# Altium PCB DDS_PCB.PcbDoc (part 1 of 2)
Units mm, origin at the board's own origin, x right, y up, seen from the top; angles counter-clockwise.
Board outline 101.55 x 88.3 mm, 8 copper layers (TOP_L1, Plane_L2, Inner_L3, Plane_L4, Plane_L5, Inner_L6, Plane_L7, Bottom Layer_L8), stack 0.681 mm thick; 432 components, 249 nets, 1457 pads, 24 vias.
Unrouted connection lines stored in the file: 980.
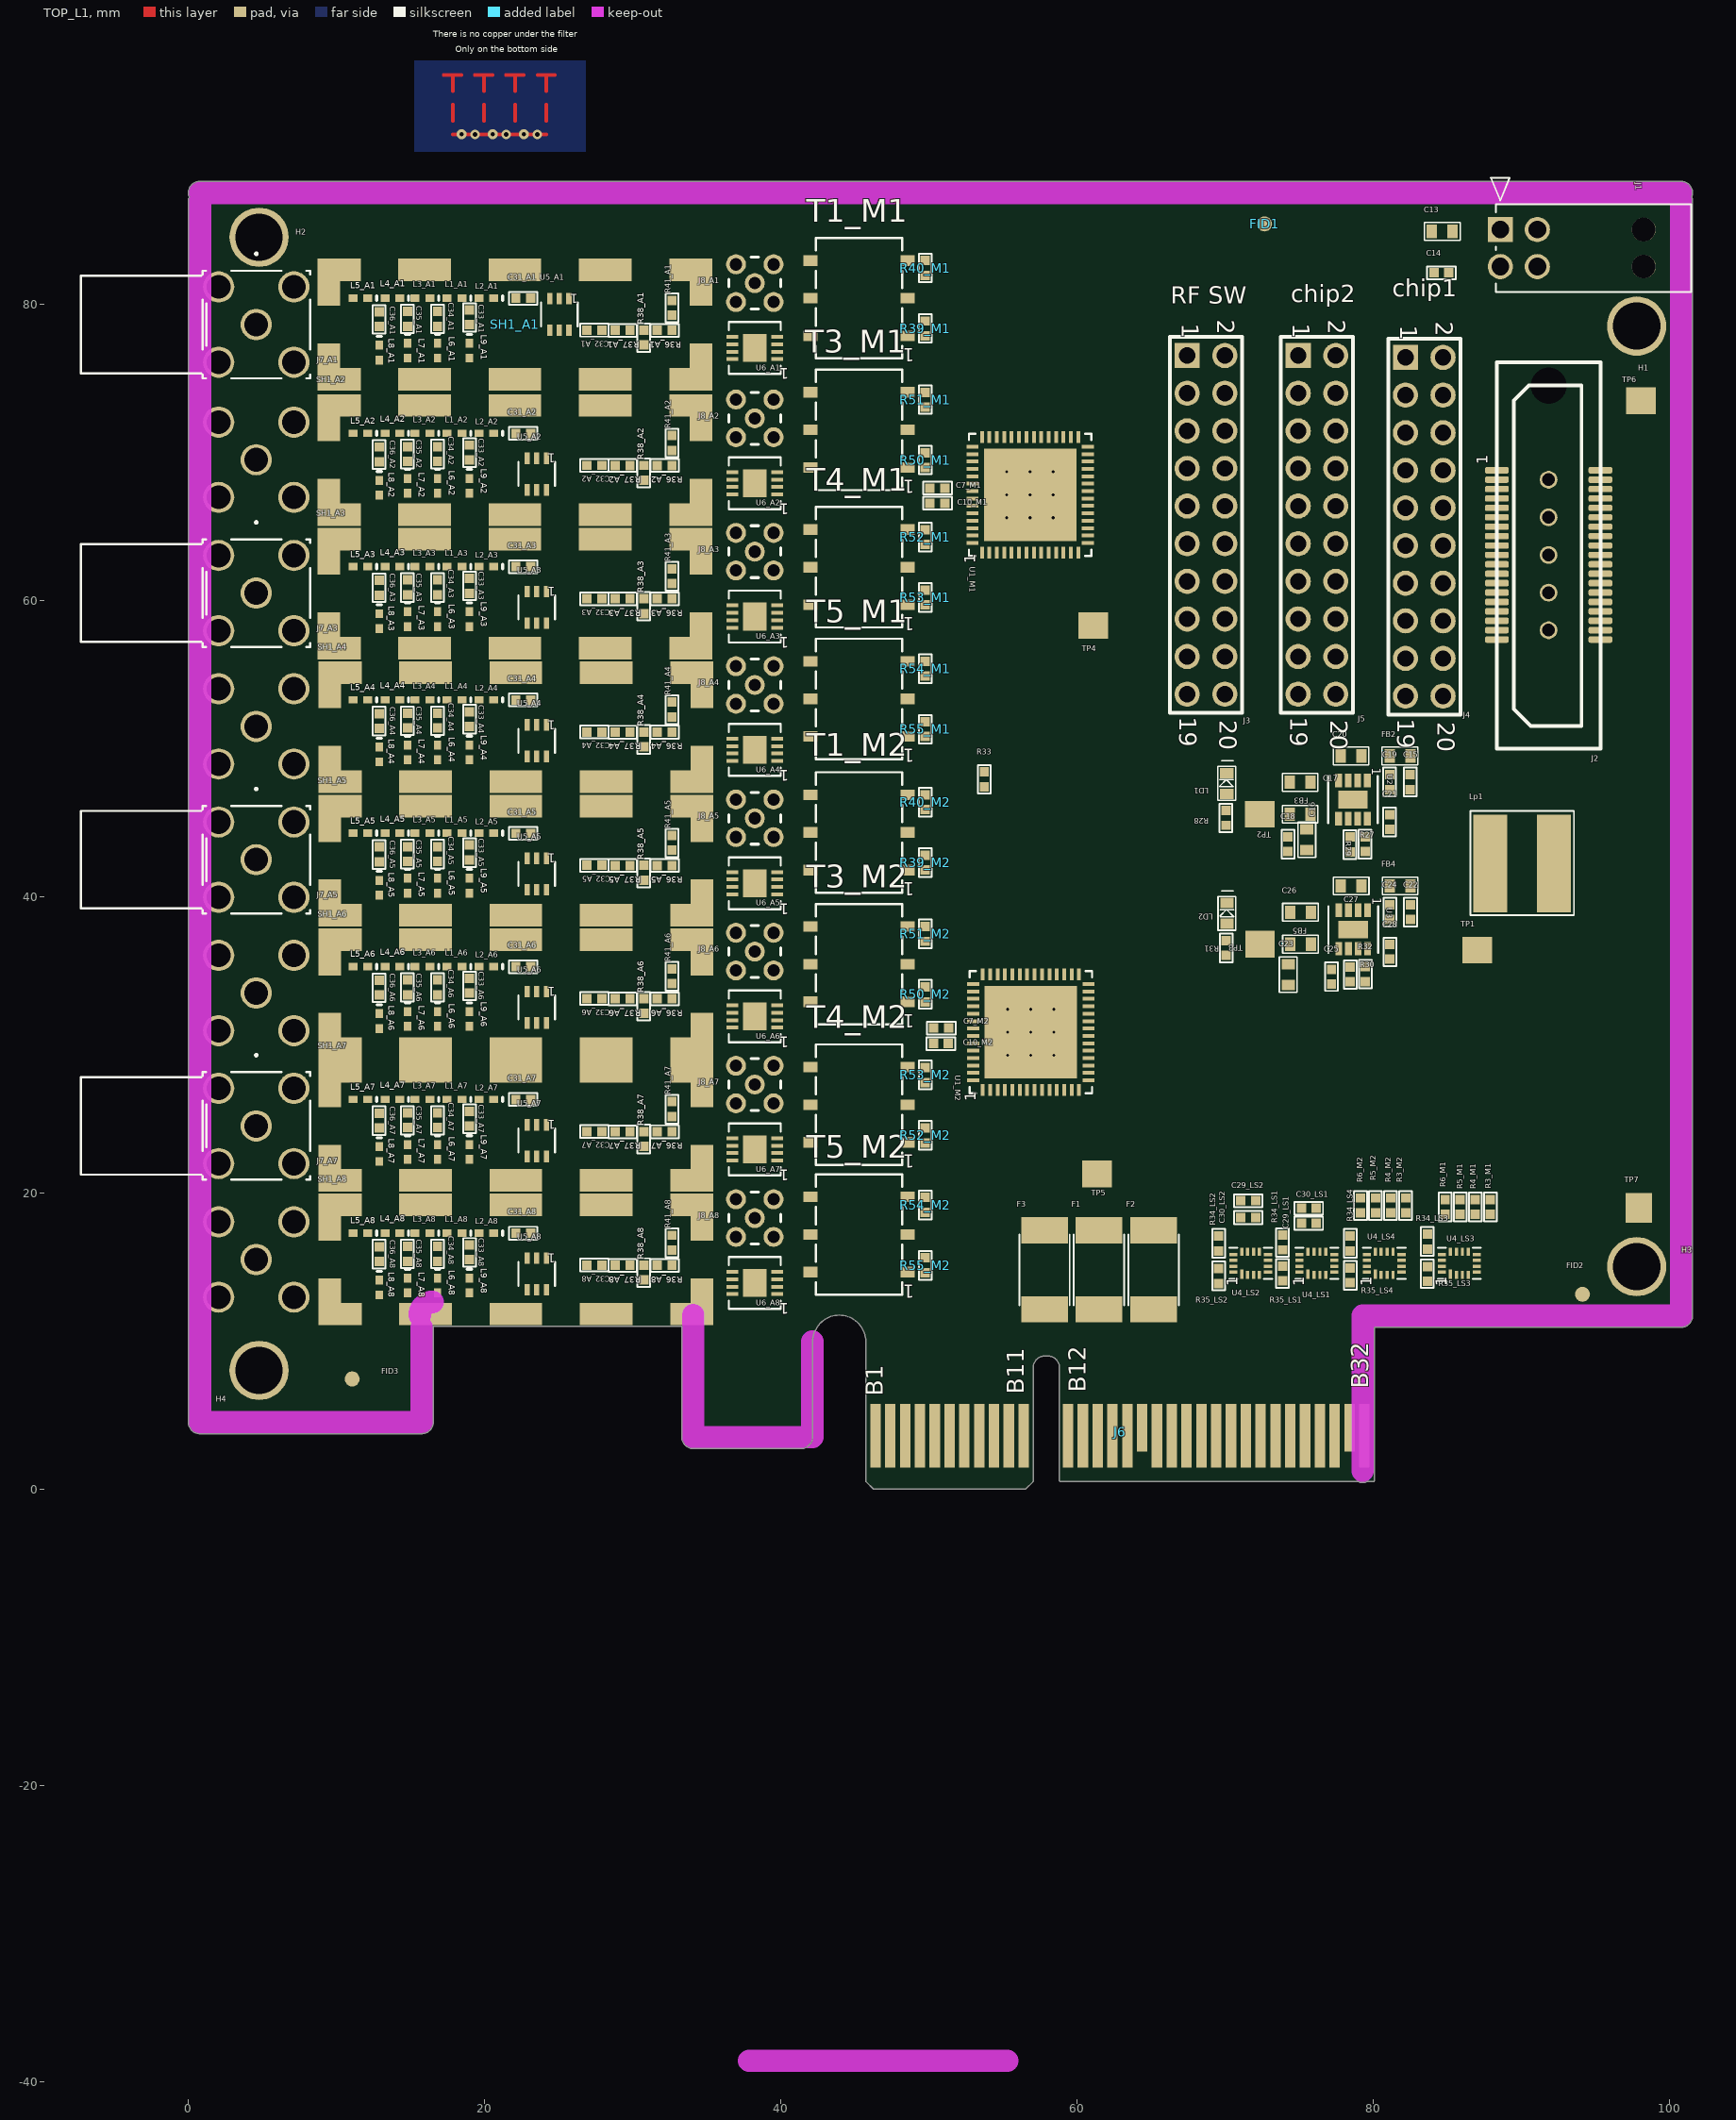
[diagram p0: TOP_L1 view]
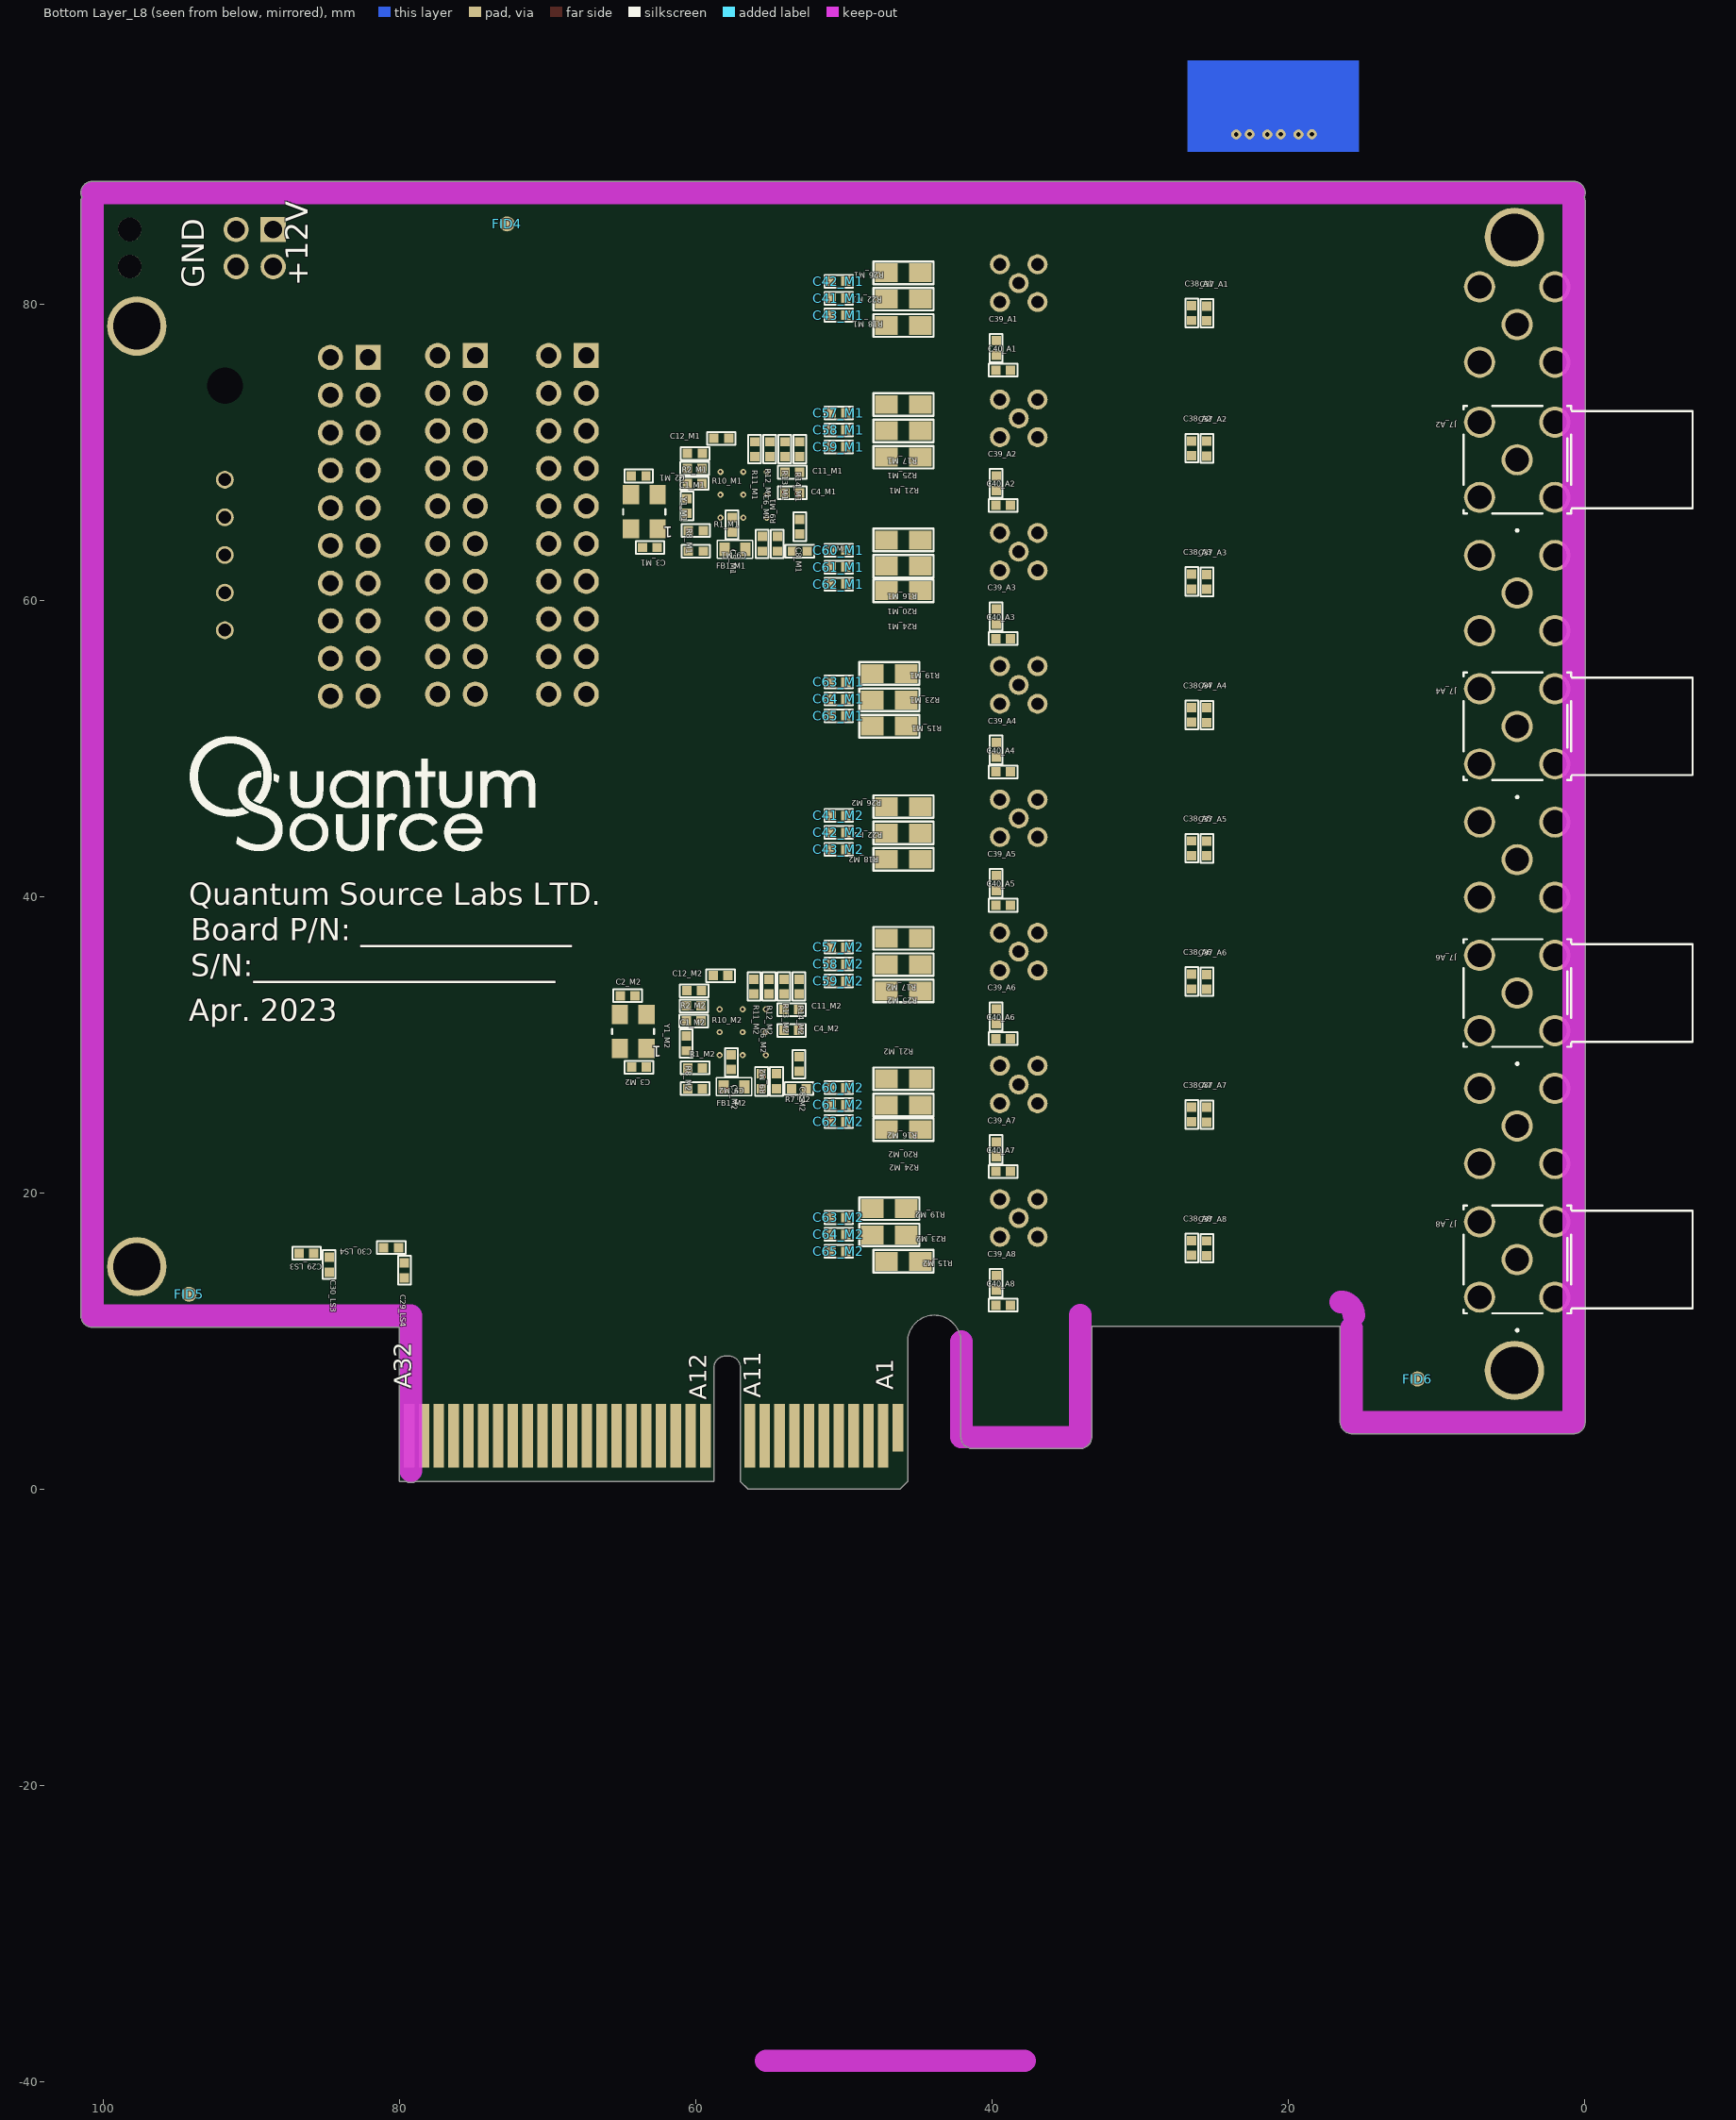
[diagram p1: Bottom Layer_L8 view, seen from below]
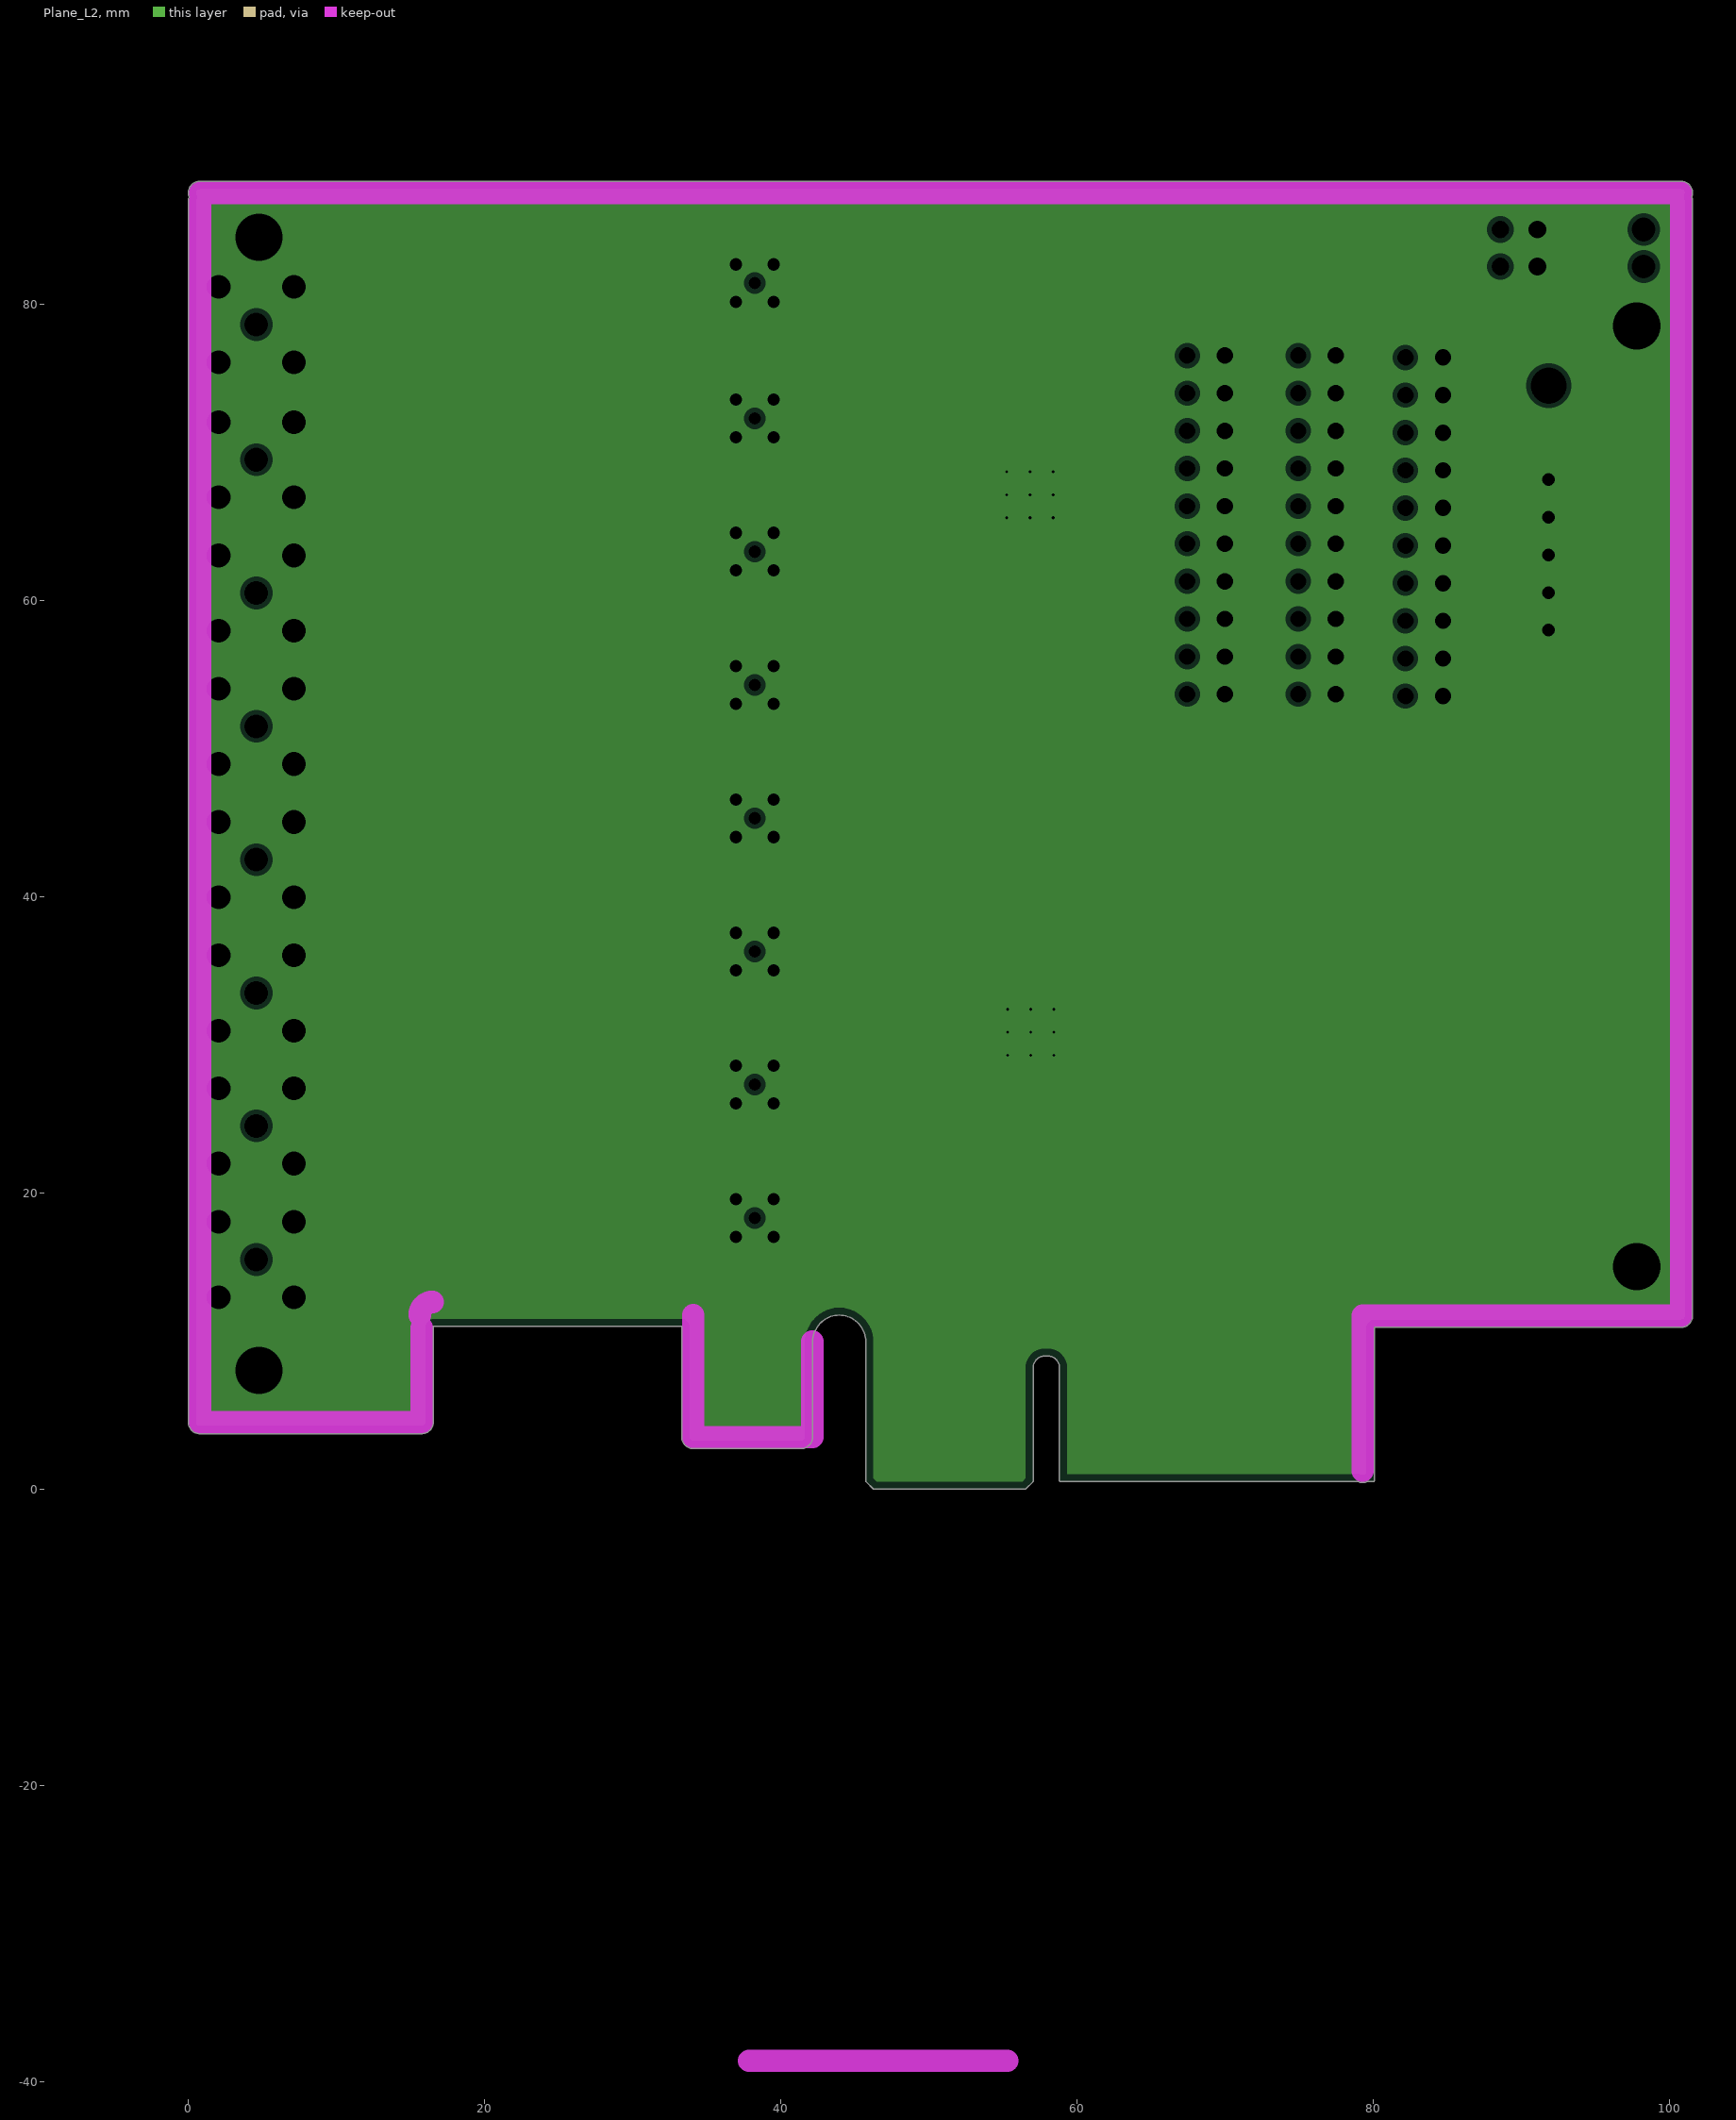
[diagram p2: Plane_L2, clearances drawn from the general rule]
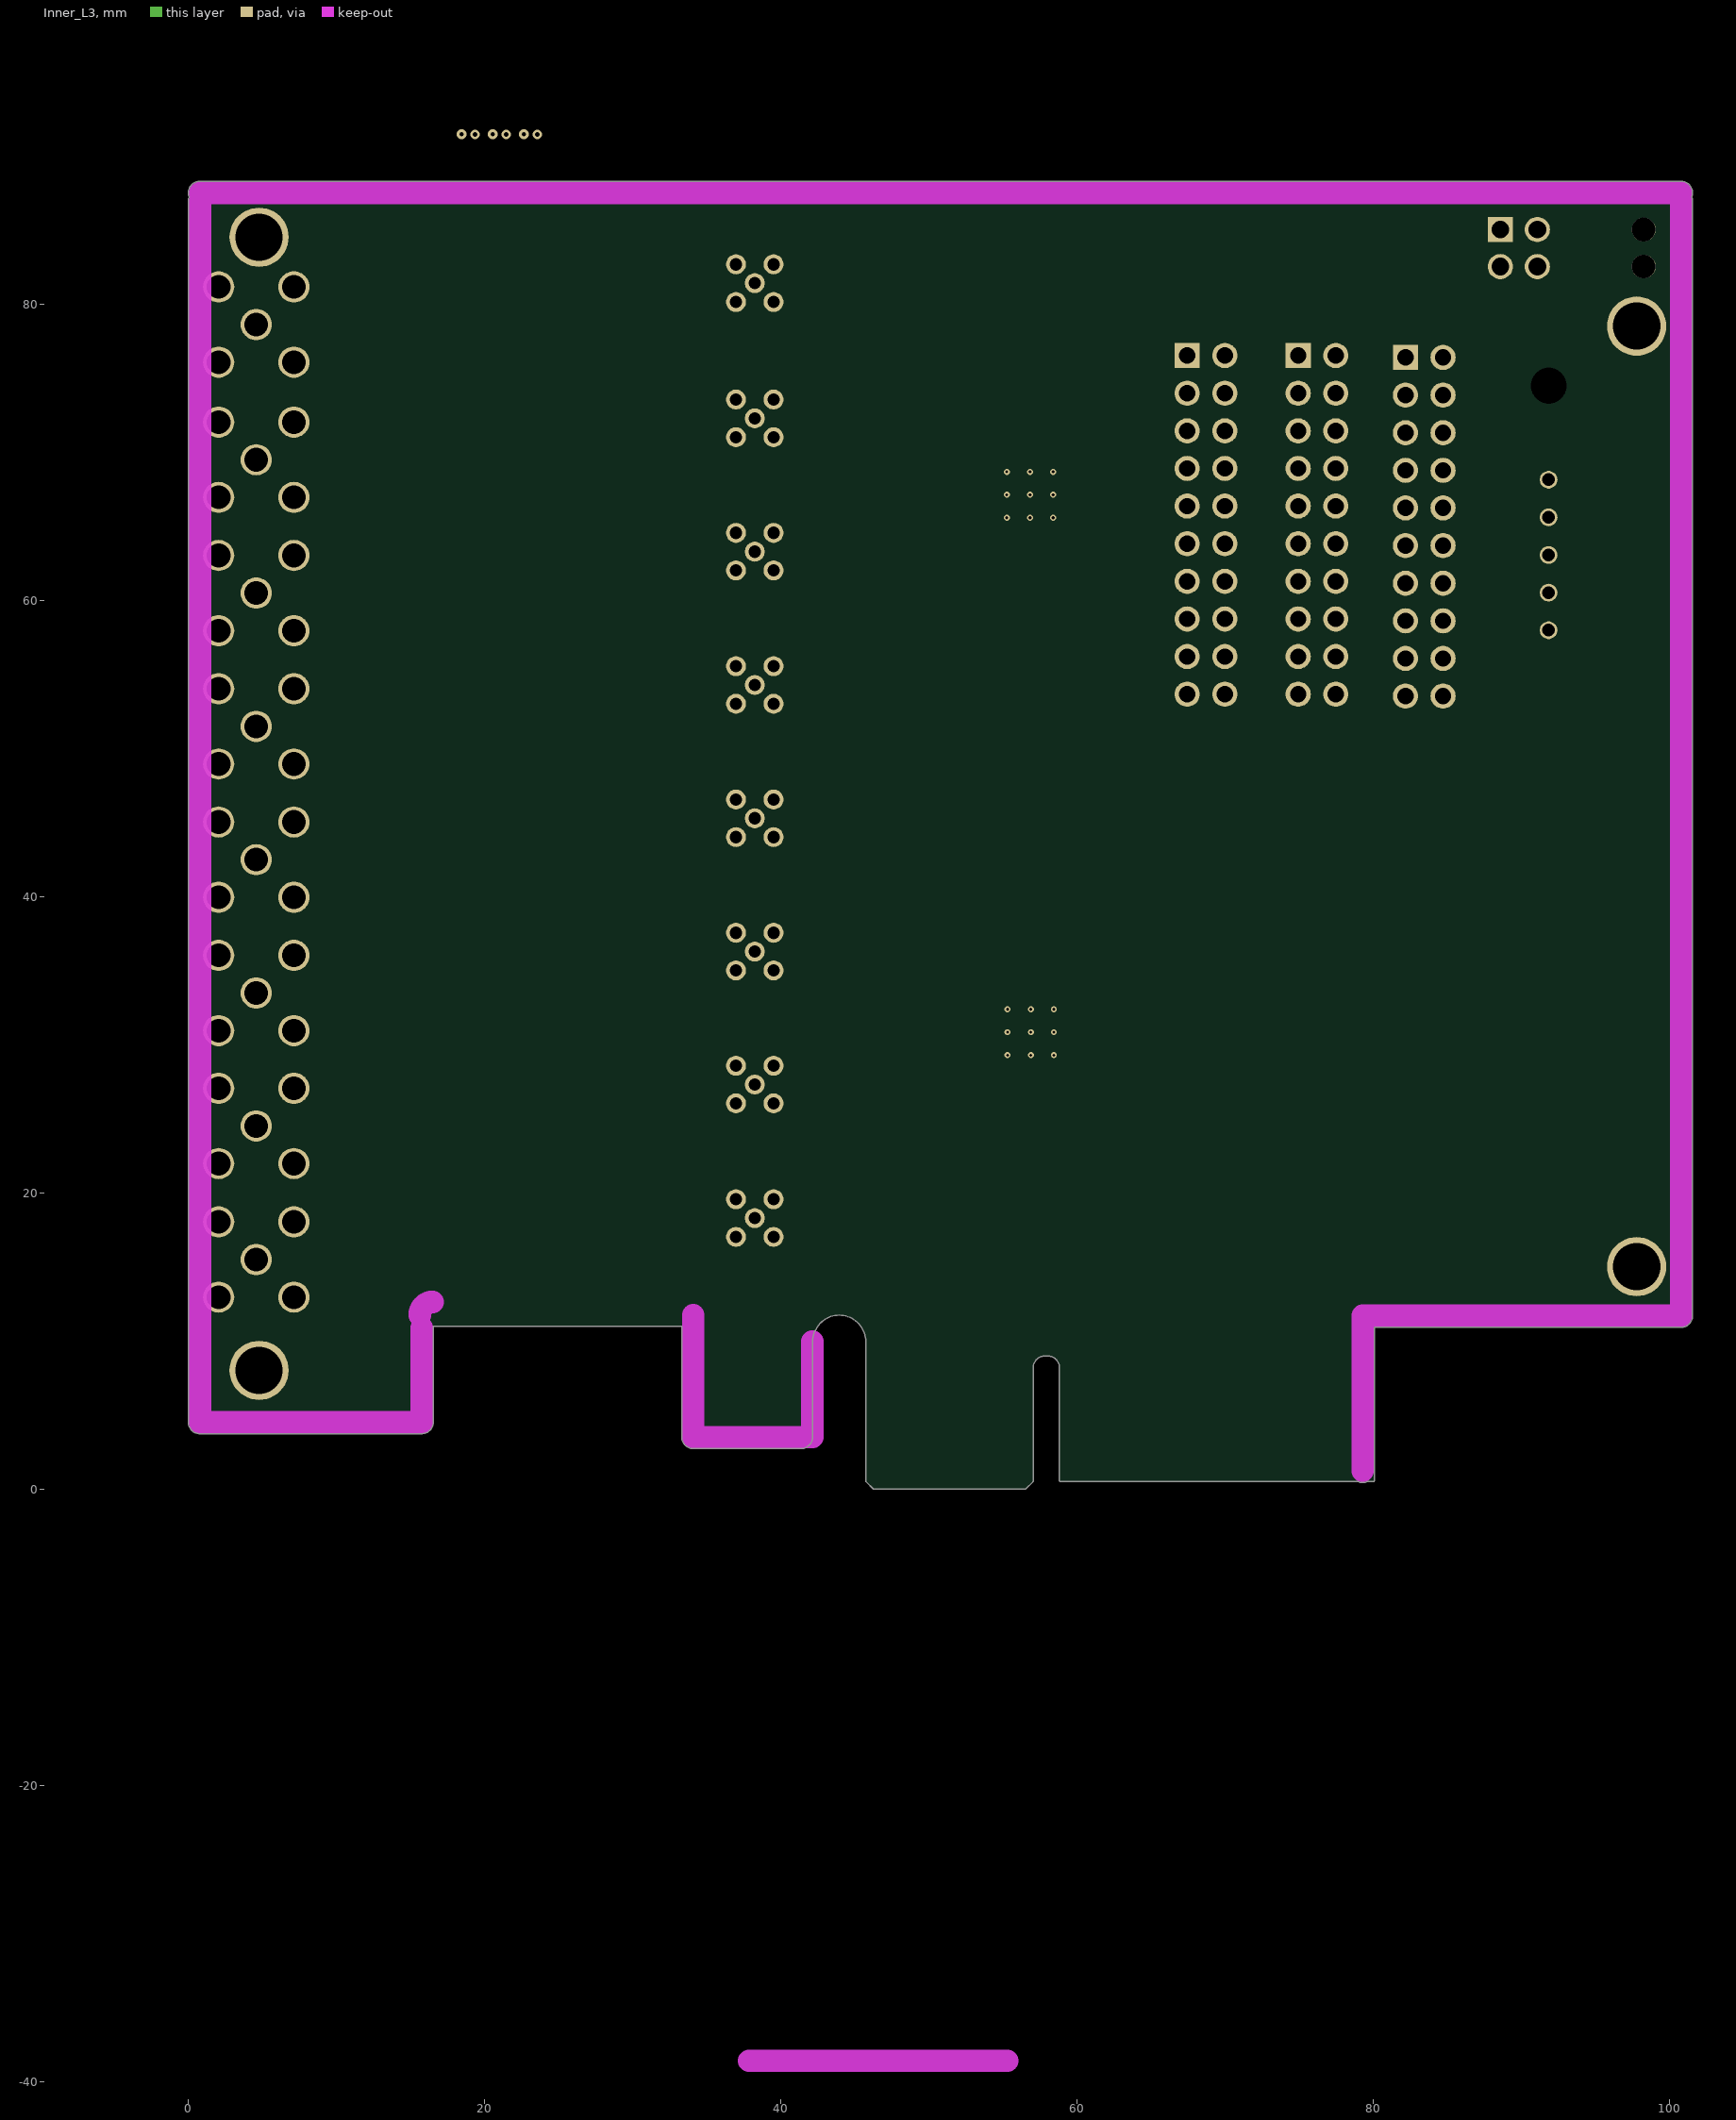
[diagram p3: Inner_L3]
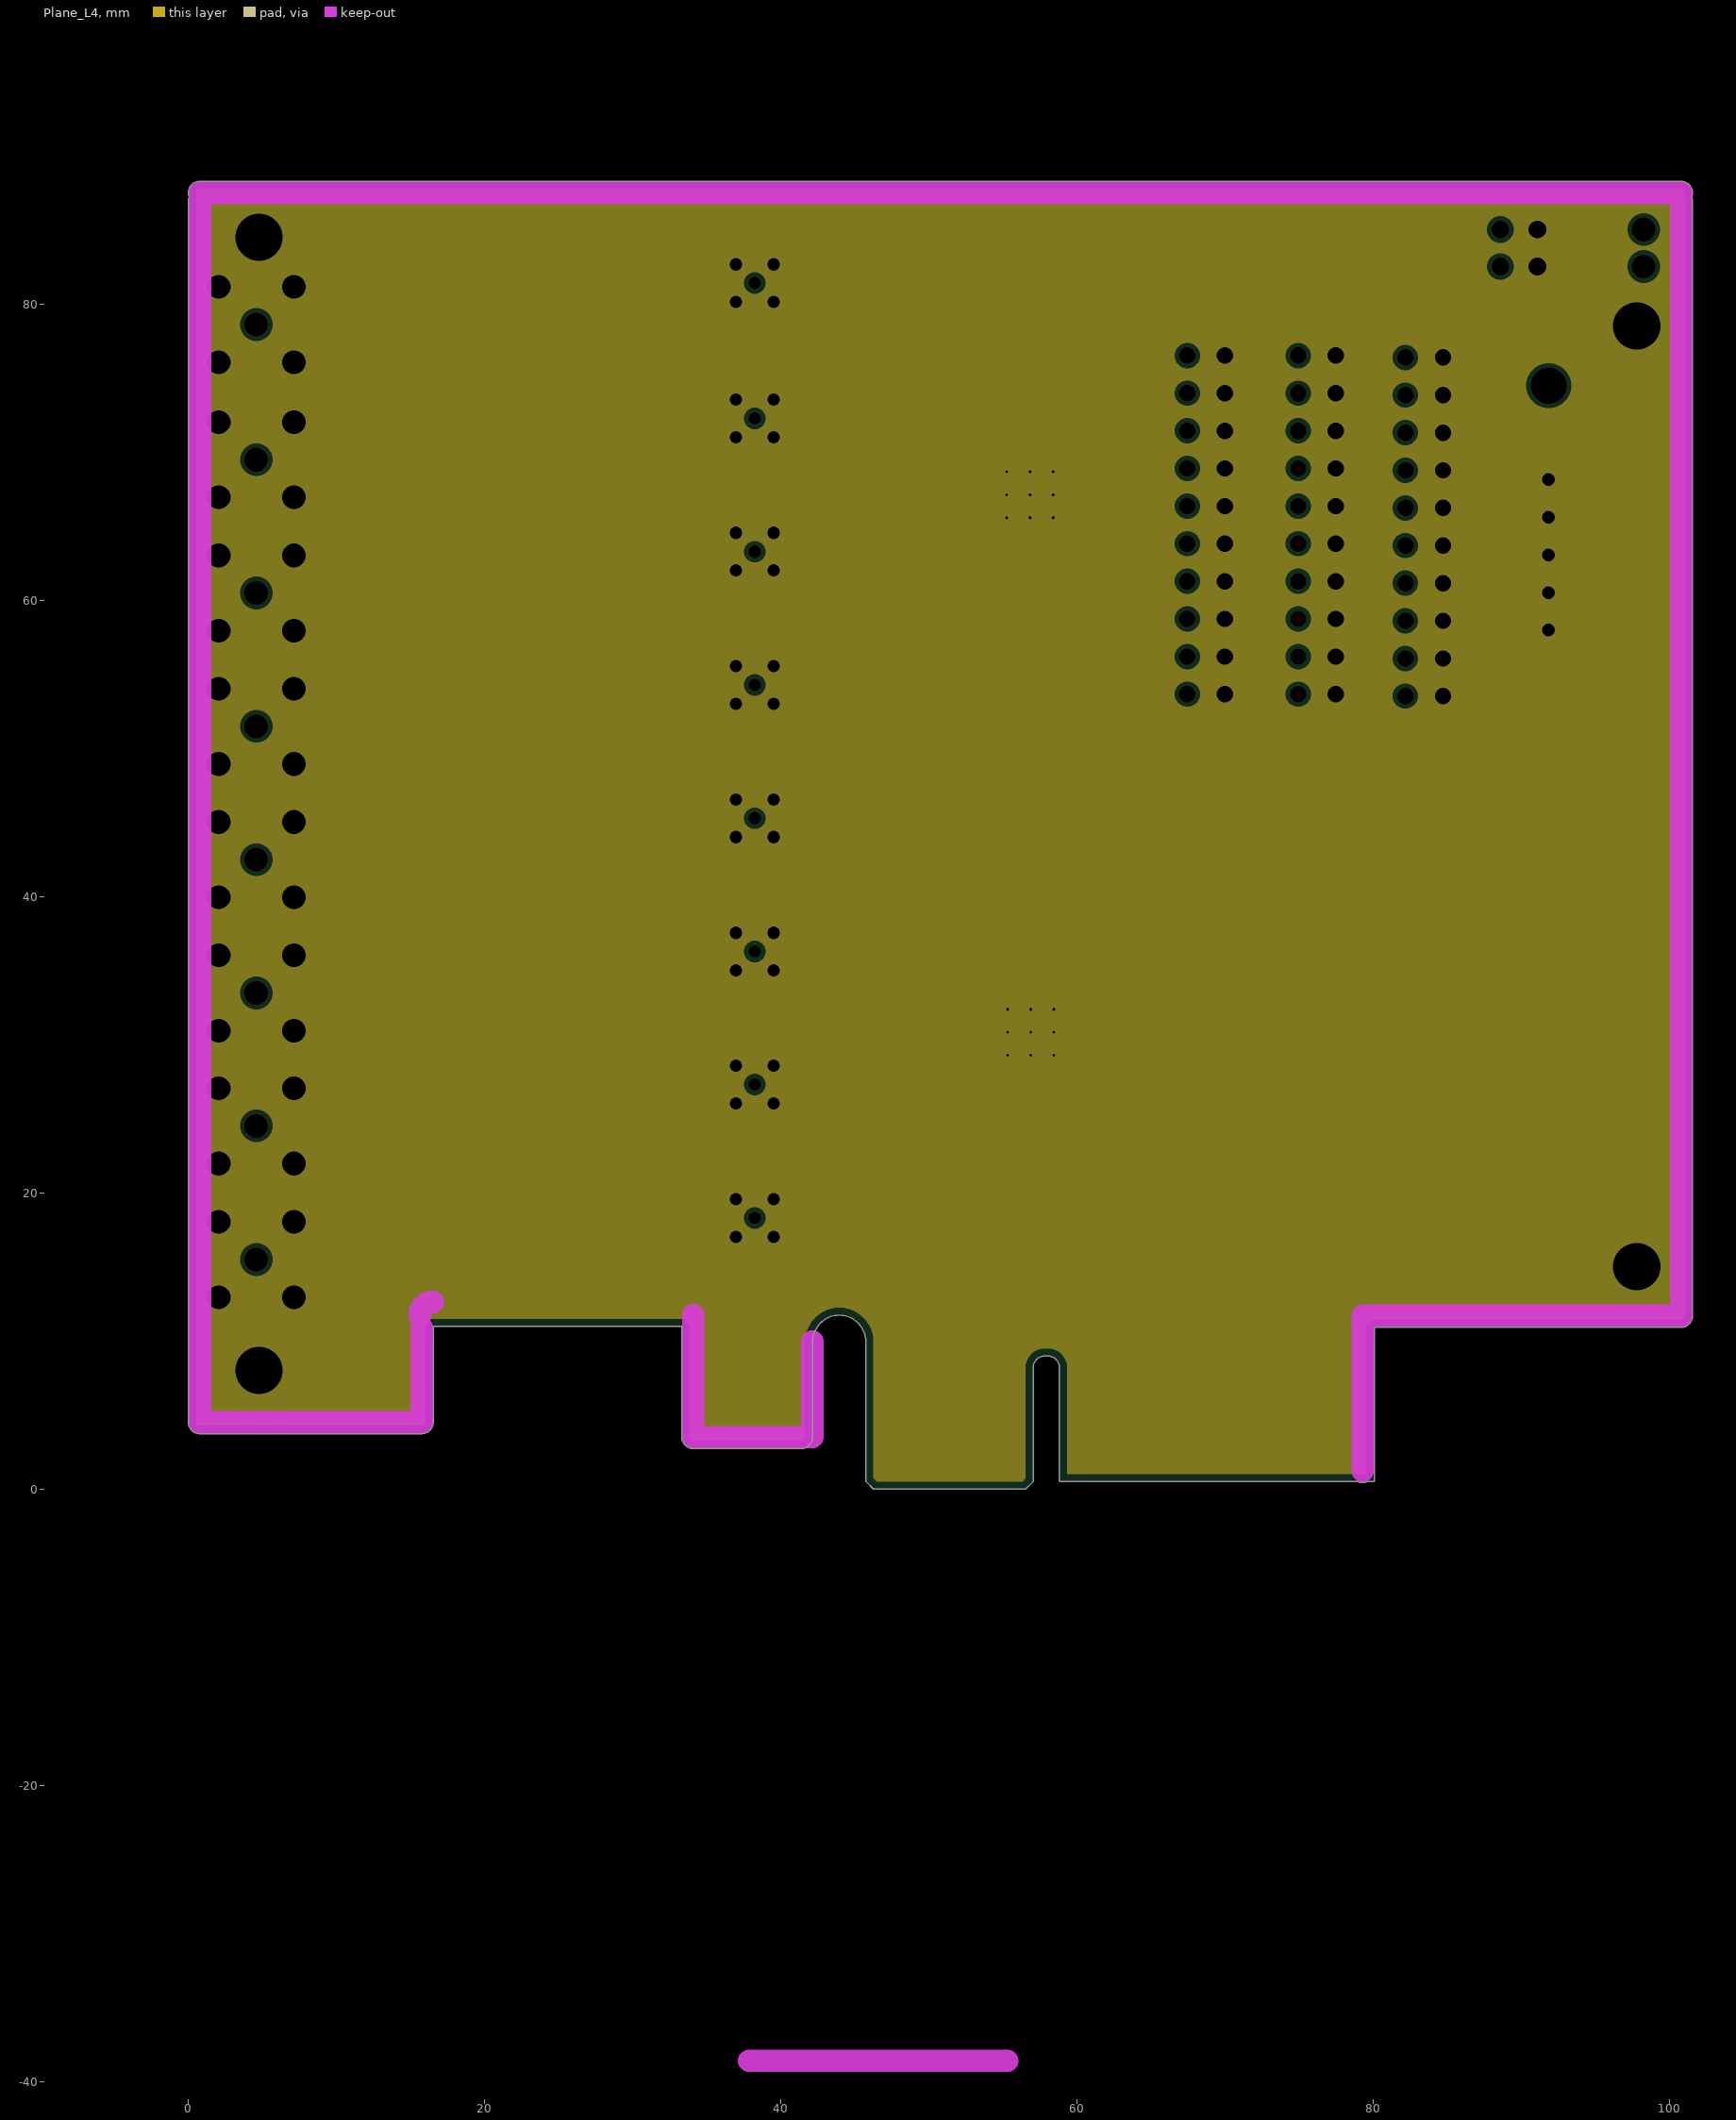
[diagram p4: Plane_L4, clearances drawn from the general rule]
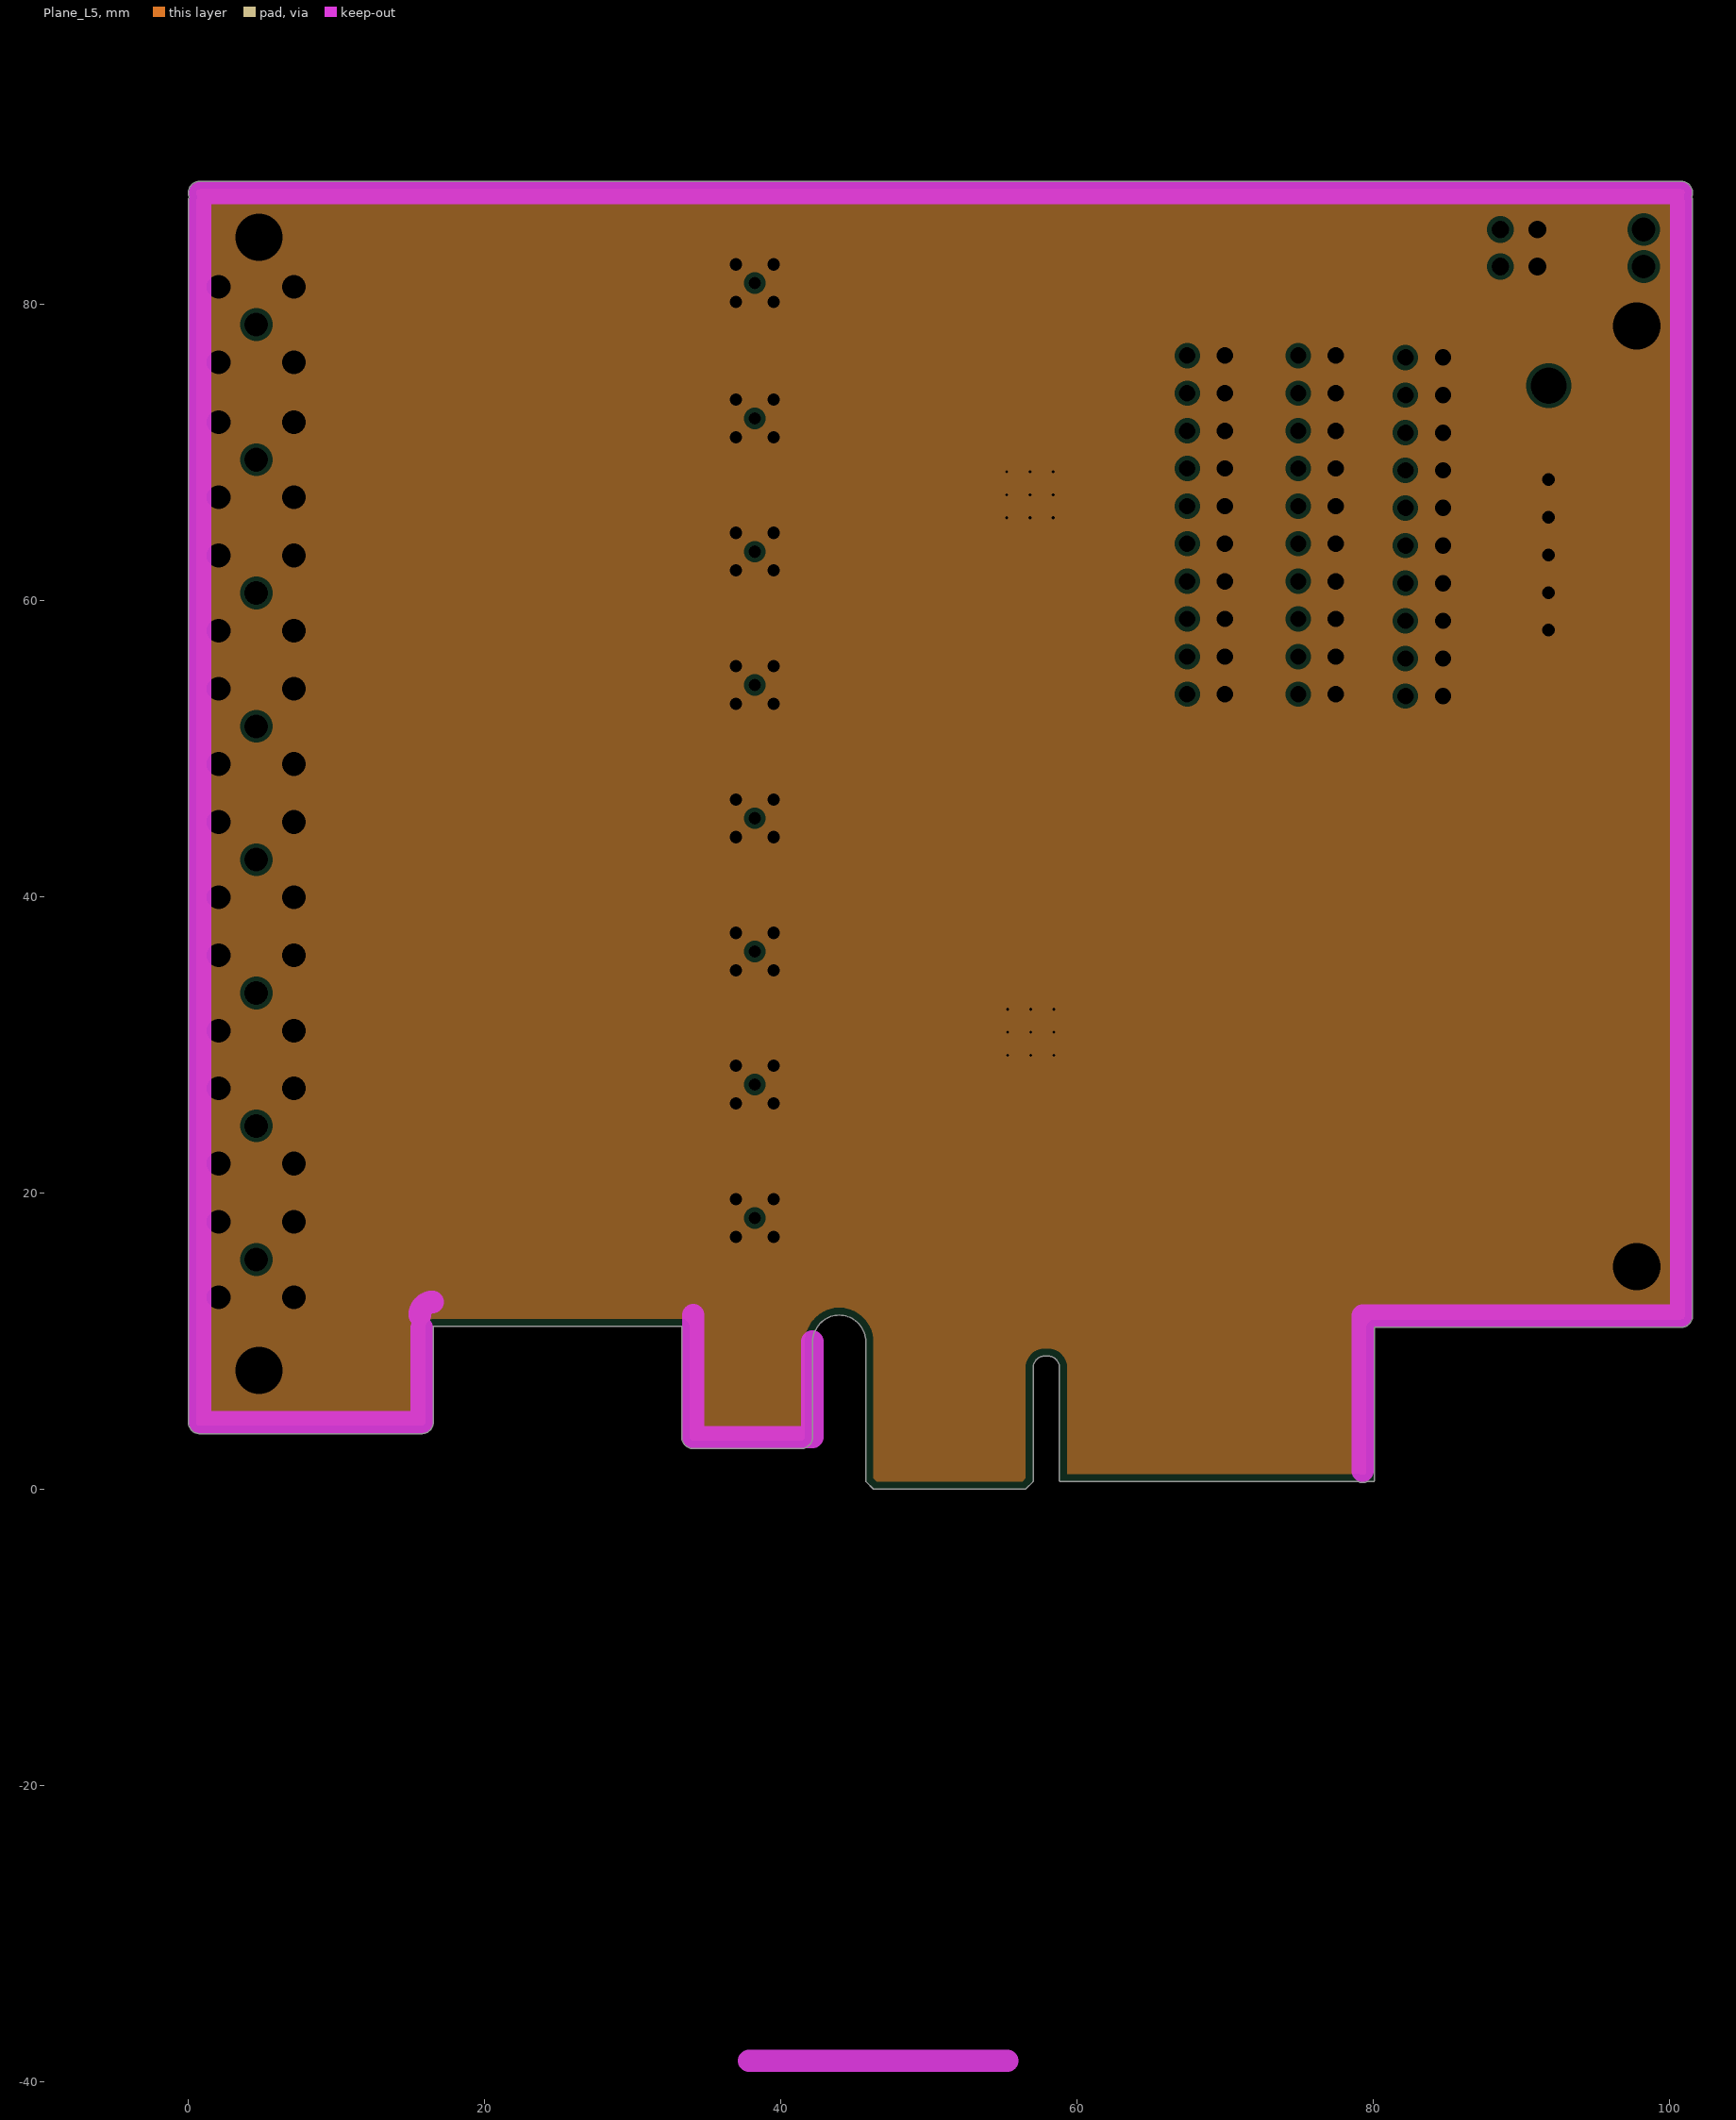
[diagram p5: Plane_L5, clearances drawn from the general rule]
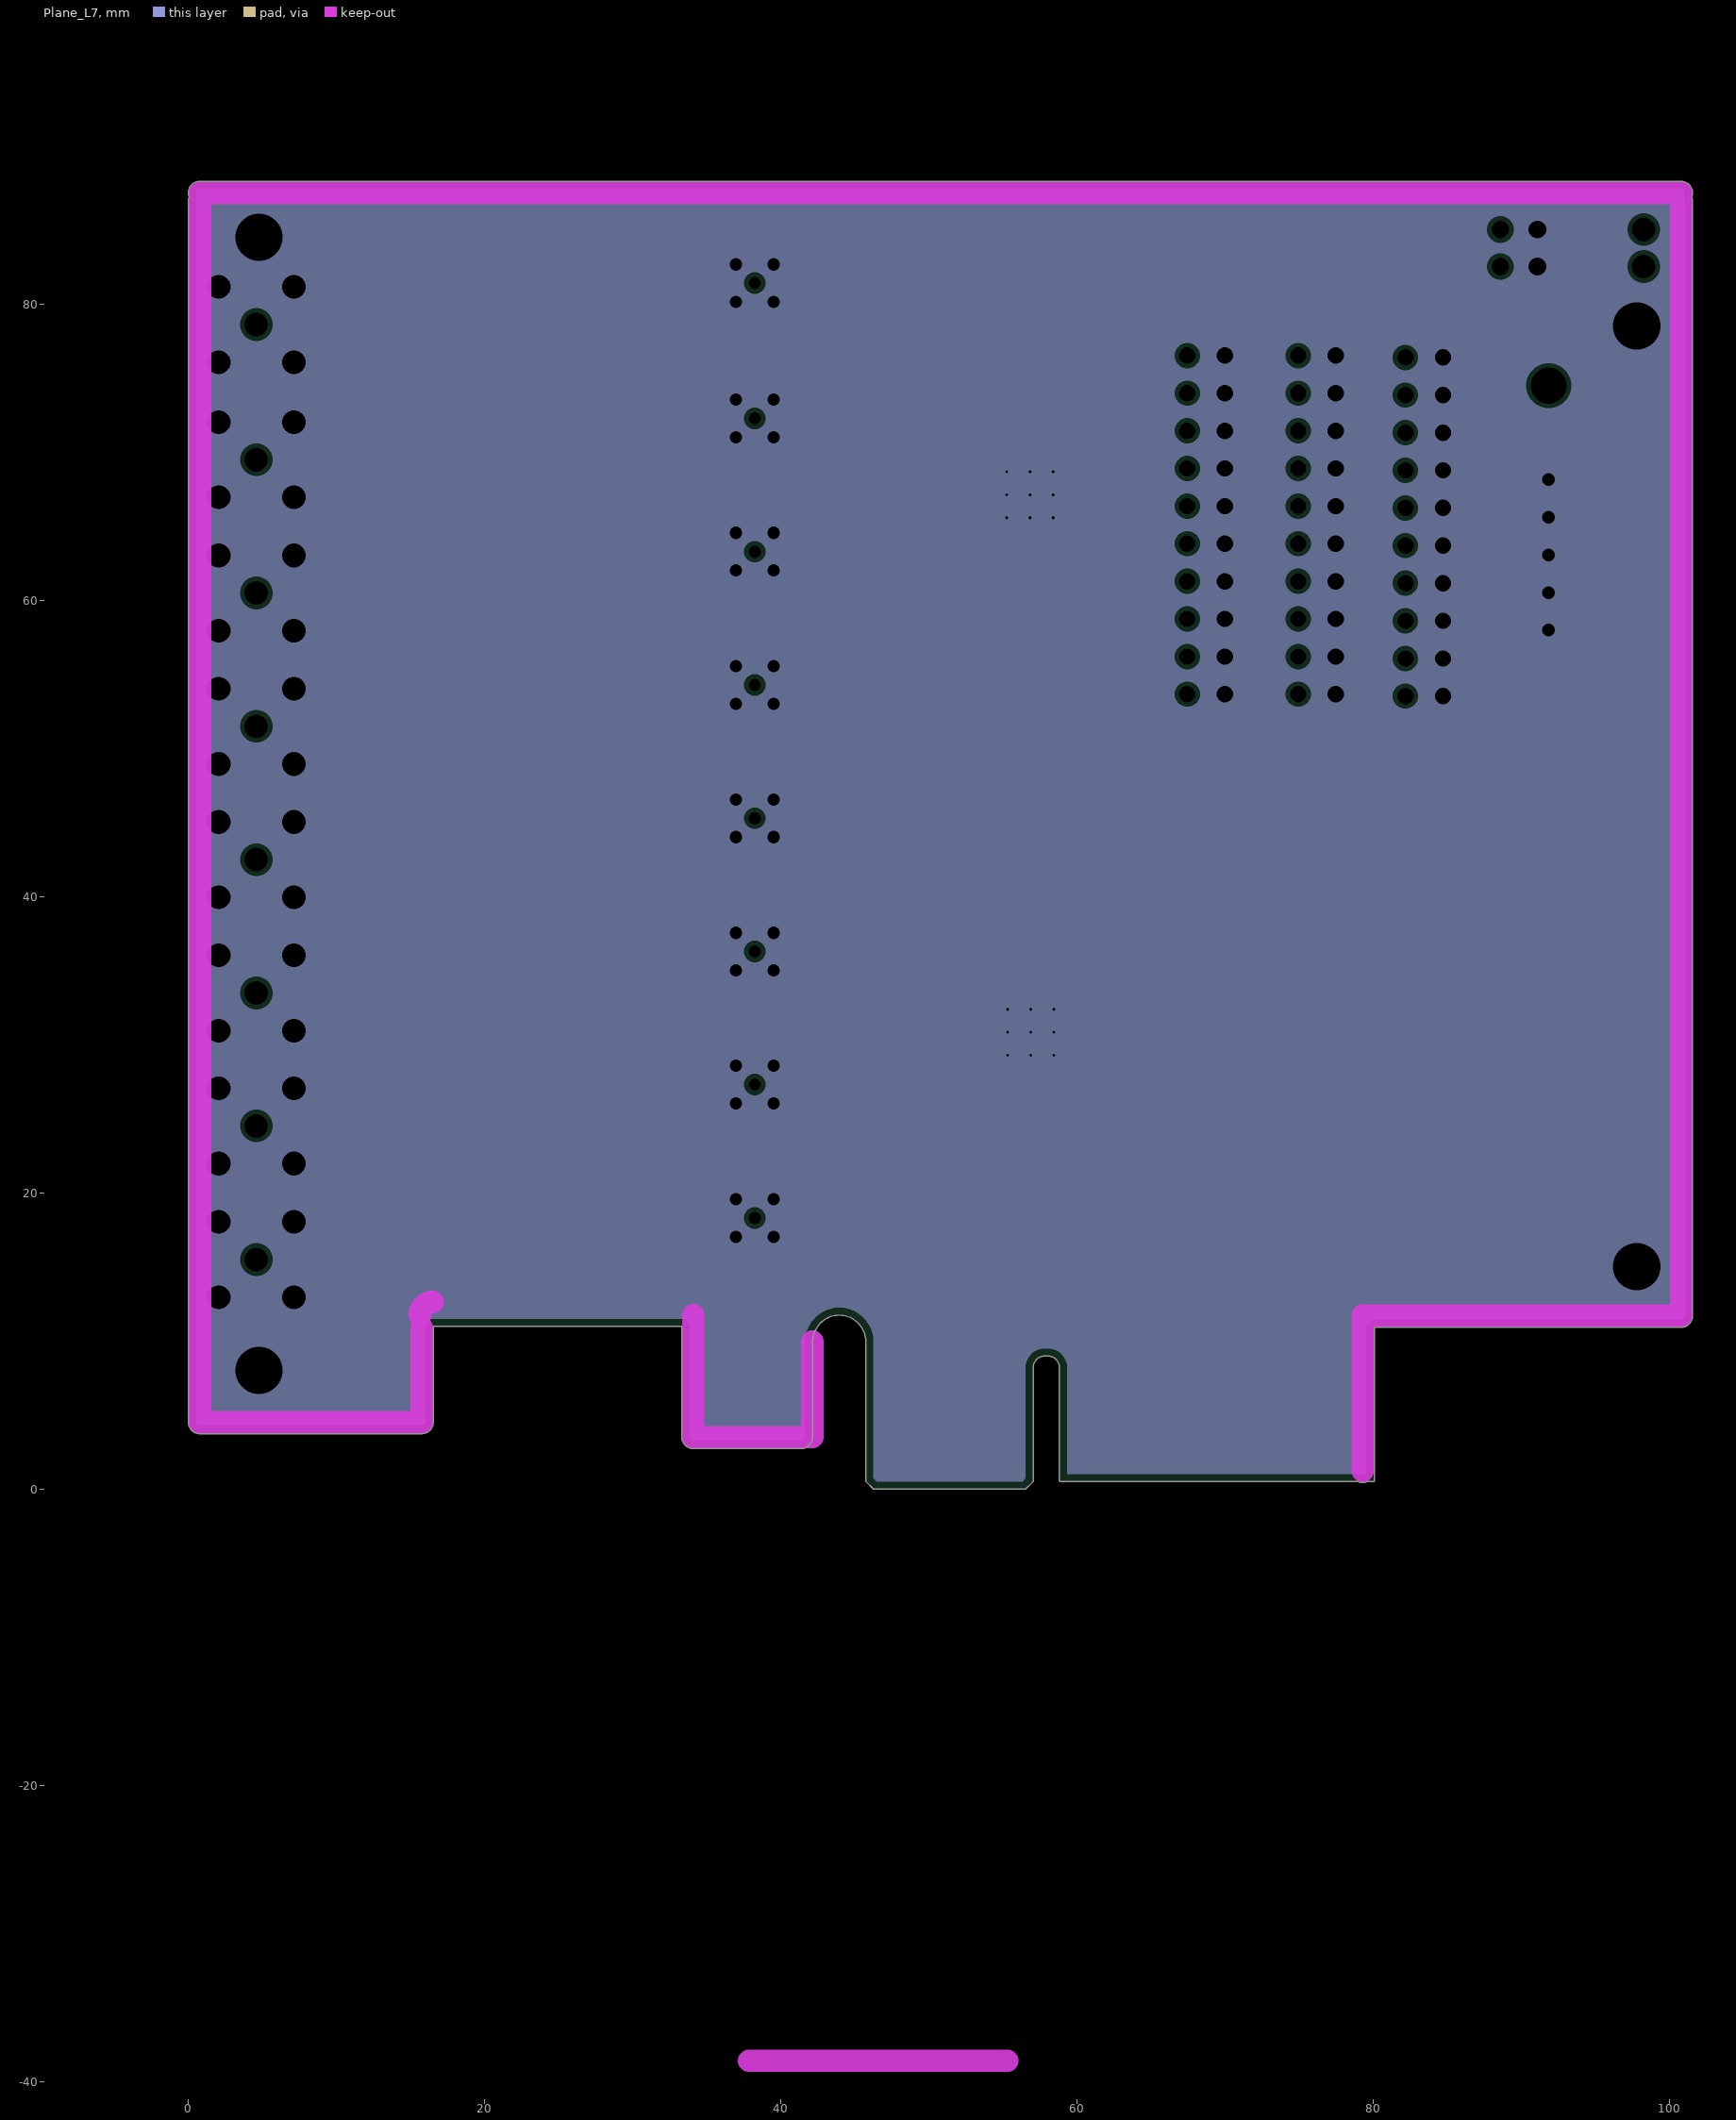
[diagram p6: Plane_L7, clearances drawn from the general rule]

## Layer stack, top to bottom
Top Solder: solder mask 0.0102, Solder Resist, Dk 3.5
TOP_L1: signal copper 0.0152
Dielectric1: core 0.0737, FR-4, Dk 3.2
Plane_L2: plane copper 0.0178, net GND
Dielectric7: prepreg 0.0762, FR-4, Dk 3.3
Inner_L3: signal copper 0.0178
Dielectric4: core 0.0711, FR-4, Dk 3.1
Plane_L4: plane copper 0.0305, net GND
Dielectric10: prepreg 0.0762, FR-4, Dk 3.3
Plane_L5: plane copper 0.0305, net GND
Dielectric 1: core 0.0711, FR-4, Dk 3.1
Inner_L6: signal copper 0.0178
Dielectric 6: prepreg 0.0762, FR-4, Dk 3.3
Plane_L7: plane copper 0.0178, net GND
Dielectric 7: core 0.0737, FR-4, Dk 3.2
Bottom Layer_L8: signal copper 0.0152
Board Layer Stack Bottom Solder: solder mask 0.0102, Solder Resist, Dk 3.5

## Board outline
0.762,3.734 cw(c0.762,4.509) -0.013,4.509 -0.013,86.932 cw(c0.762,86.932) 0.043,87.221 cw(c0.762,87.509) 0.762,88.285 100.762,88.285 cw(c100.762,87.509) 101.538,87.509 cw(c100.762,87.509) 101.482,87.221 cw(c100.762,86.932) 101.538,86.933 101.538,86.932 101.538,11.694 cw(c100.762,11.694) 100.762,10.919 80.053,10.919 80.053,0.522 80.026,0.496 79.569,0.496 cw(c79.264,1.209) 78.96,0.496 58.826,0.496 58.8,0.522 58.8,8.187 ccw(c58.009,8.187) 58.009,8.978 57.815,8.978 ccw(c57.815,8.183) 57.021,8.183 57.021,0.513 57.013,0.495 56.509,-0.009 56.491,-0.017 46.262,-0.017 46.244,-0.009 45.737,0.492 45.723,0.517 45.723,9.937 ccw(c43.927,9.937) 43.927,11.734 43.926,11.734 ccw(c43.926,9.959) 42.309,10.69 42.292,10.683 ccw(c43.926,9.937) 42.13,9.937 42.13,3.514 42.13,3.512 cw(c41.342,3.512) 41.342,2.724 34.087,2.724 cw(c34.087,3.512) 33.298,3.512 33.298,10.974 16.526,10.974 16.526,4.522 cw(c15.737,4.522) 15.737,3.734

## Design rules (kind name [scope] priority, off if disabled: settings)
Clearance [All] p1: gap=0.203 ignorepadtopadclearanceinfootprint=FALSE except(0: Arc-Hole Track-Hole SMDPad-Hole THPad-Hole Via-Hole Fill-Hole Poly-Hole Region-Hole Text-Hole)
DiffPairsRouting DiffPair_100OhmDiffPairsRouting [InDifferentialPairClass('New Class_100Ohm')] p1: maxlimit=0.165 minlimit=0.152 mostfreqgap=0.165 toplayer_maxgap=0.152 toplayer_prefgap=0.152 toplayer_minwidth=0.381 toplayer_maxwidth=0.381 toplayer_prefwidth=0.381 midlayer2_mingap=0.165 midlayer2_minwidth=0.381 midlayer2_maxwidth=0.381 midlayer2_prefwidth=0.381 midlayer4_mingap=0.165 midlayer4_minwidth=0.381 midlayer4_maxwidth=0.381 midlayer4_prefwidth=0.381 bottomlayer_maxgap=0.152 bottomlayer_prefgap=0.152 bottomlayer_minwidth=0.381 bottomlayer_maxwidth=0.381 bottomlayer_prefwidth=0.381 maxuncoupledlength=12.7
Length Length_GPIO2_[0..15] [InNetClass('GPIO2_[0..15]')] p1: maxlimit=41.351 minlimit=40.64
Length Length_DDR3_A0-15_control [InNetClass('DDR3_A[0..15]_CONTROL')] p2: maxlimit=60.985 minlimit=60.96
Length Length_SSF_TD1-6 [InDifferentialPairClass('New Class_SSF_TD1-6')] p3: maxlimit=268.707 minlimit=268.681
Length Length_PCI_RX0-7 [InDifferentialPairClass('New Class_PCI_RX0-6')] p4: maxlimit=66.065 minlimit=66.04
Length Length_PCI_TX0-7 [InDifferentialPairClass('New Class_PCI_TX0-6')] p5: maxlimit=51.206 minlimit=51.181
MatchedLengths DiffPair_85OhmMatchedLengths [All] p1: tolerance=0.635 checknetsindiffpair=TRUE checkdiffpairvsdiffpair=FALSE checkxsignals=FALSE checkothers=FALSE
MatchedLengths DiffPair_80OhmMatchedLengths [All] p2: tolerance=0.635 checknetsindiffpair=TRUE checkdiffpairvsdiffpair=FALSE checkxsignals=FALSE checkothers=FALSE
MatchedLengths DiffPair_100OhmMatchedLengths [All] p3: tolerance=0.635 checknetsindiffpair=TRUE checkdiffpairvsdiffpair=FALSE checkxsignals=FALSE checkothers=FALSE
PlaneClearance [All] p1: clearance=0.305
PlaneConnect PlaneConnect_Via [Isvia] p1: planeconnectstyle=Direct reliefexpansion=0.508 reliefentries=4 reliefconductorwidth=0.254 reliefairgap=0.254
PlaneConnect [All] p2: planeconnectstyle=Relief reliefexpansion=0.508 reliefentries=4 reliefconductorwidth=0.508 reliefairgap=0.203
PolygonConnect PolygonConnect_1PWRPAD [InPadClass('New Class_PWRpad')] p1: connectstyle=Direct reliefconductorwidth=0.254 reliefentries=4 polygonreliefangle="90 Angle" airgapwidth=0.254
PolygonConnect PolygonConnect_PWR [InComponentClass('New Class_pwr')] p2: connectstyle=Relief reliefconductorwidth=0.762 reliefentries=4 polygonreliefangle="90 Angle" airgapwidth=0.254
PolygonConnect PolygonConnect_Via [Isvia] p3: connectstyle=Direct reliefconductorwidth=0.254 reliefentries=4 polygonreliefangle="90 Angle" airgapwidth=0.254
PolygonConnect PolygonConnect_TPs [InComponentClass('New Class_TPs')] p4: connectstyle=Direct reliefconductorwidth=0.254 reliefentries=4 polygonreliefangle="90 Angle" airgapwidth=0.254
PolygonConnect [All] p5: connectstyle=Relief reliefconductorwidth=0.508 reliefentries=4 polygonreliefangle="90 Angle" airgapwidth=0.254
RoomDefinition A6 [InComponentClass('A6')] p1: confinementstyle=ConfineIn formatcopy=TRUE lockcomponents=FALSE outline -7.62,28.737 40.894,28.737 40.894,39.024 -7.62,39.024
RoomDefinition A7 [InComponentClass('A7')] p2: confinementstyle=ConfineIn formatcopy=TRUE lockcomponents=FALSE outline -7.62,19.762 40.894,19.762 40.894,30.049 -7.62,30.049
RoomDefinition A1 [InComponentClass('A1')] p3: confinementstyle=ConfineIn formatcopy=TRUE lockcomponents=FALSE outline -7.62,73.864 40.894,73.864 40.894,84.151 -7.62,84.151
RoomDefinition A2 [InComponentClass('A2')] p4: confinementstyle=ConfineIn formatcopy=TRUE lockcomponents=FALSE outline -7.62,64.737 40.894,64.737 40.894,75.024 -7.62,75.024
RoomDefinition A8 [InComponentClass('A8')] p5: confinementstyle=ConfineIn formatcopy=TRUE lockcomponents=FALSE outline -7.62,10.745 40.894,10.745 40.894,21.032 -7.62,21.032
RoomDefinition A5 [InComponentClass('A5')] p6: confinementstyle=ConfineIn formatcopy=TRUE lockcomponents=FALSE outline -7.62,37.737 40.894,37.737 40.894,48.024 -7.62,48.024
RoomDefinition A4 [InComponentClass('A4')] p7: confinementstyle=ConfineIn formatcopy=TRUE lockcomponents=FALSE outline -7.62,46.737 40.894,46.737 40.894,57.024 -7.62,57.024
RoomDefinition A3 [InComponentClass('A3')] p8: confinementstyle=ConfineIn formatcopy=TRUE lockcomponents=FALSE outline -7.62,55.737 40.894,55.737 40.894,66.024 -7.62,66.024
RoutingVias [All] p1: holewidth=0.254 width=0.508 viastyle="Through Hole" minholewidth=0.254 minwidth=0.508 maxholewidth=0.711 maxwidth=1.27
SilkToSolderMaskClearance SilkscreenOverComponentPads [IsPad] p1: minsilkscreentomaskgap=0.254 clearancetoexposedcopper=TRUE
SolderMaskExpansion [All] p1: expansion=0.102 istentingtop=FALSE
Width [All] p1: maxlimit=2.54 minlimit=0.152 preferedwidth=0.203
26 further rules are at their usual default settings.

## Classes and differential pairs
component class A8: C31_A8 C32_A8 C33_A8 C34_A8 C35_A8 C36_A8 C37_A8 C38_A8 C39_A8 C40_A8 J7_A8 J8_A8 L1_A8 L2_A8 L3_A8 L4_A8 L5_A8 L6_A8 L7_A8 L8_A8 L9_A8 R36_A8 R37_A8 R38_A8 R41_A8 SH1_A8 U5_A8 U6_A8
component class A7: C31_A7 C32_A7 C33_A7 C34_A7 C35_A7 C36_A7 C37_A7 C38_A7 C39_A7 C40_A7 J7_A7 J8_A7 L1_A7 L2_A7 L3_A7 L4_A7 L5_A7 L6_A7 L7_A7 L8_A7 L9_A7 R36_A7 R37_A7 R38_A7 R41_A7 SH1_A7 U5_A7 U6_A7
component class A6: C31_A6 C32_A6 C33_A6 C34_A6 C35_A6 C36_A6 C37_A6 C38_A6 C39_A6 C40_A6 J7_A6 J8_A6 L1_A6 L2_A6 L3_A6 L4_A6 L5_A6 L6_A6 L7_A6 L8_A6 L9_A6 R36_A6 R37_A6 R38_A6 R41_A6 SH1_A6 U5_A6 U6_A6
component class A5: C31_A5 C32_A5 C33_A5 C34_A5 C35_A5 C36_A5 C37_A5 C38_A5 C39_A5 C40_A5 J7_A5 J8_A5 L1_A5 L2_A5 L3_A5 L4_A5 L5_A5 L6_A5 L7_A5 L8_A5 L9_A5 R36_A5 R37_A5 R38_A5 R41_A5 SH1_A5 U5_A5 U6_A5
component class A3: C31_A3 C32_A3 C33_A3 C34_A3 C35_A3 C36_A3 C37_A3 C38_A3 C39_A3 C40_A3 J7_A3 J8_A3 L1_A3 L2_A3 L3_A3 L4_A3 L5_A3 L6_A3 L7_A3 L8_A3 L9_A3 R36_A3 R37_A3 R38_A3 R41_A3 SH1_A3 U5_A3 U6_A3
component class A4: C31_A4 C32_A4 C33_A4 C34_A4 C35_A4 C36_A4 C37_A4 C38_A4 C39_A4 C40_A4 J7_A4 J8_A4 L1_A4 L2_A4 L3_A4 L4_A4 L5_A4 L6_A4 L7_A4 L8_A4 L9_A4 R36_A4 R37_A4 R38_A4 R41_A4 SH1_A4 U5_A4 U6_A4
component class A2: C31_A2 C32_A2 C33_A2 C34_A2 C35_A2 C36_A2 C37_A2 C38_A2 C39_A2 C40_A2 J7_A2 J8_A2 L1_A2 L2_A2 L3_A2 L4_A2 L5_A2 L6_A2 L7_A2 L8_A2 L9_A2 R36_A2 R37_A2 R38_A2 R41_A2 SH1_A2 U5_A2 U6_A2
component class A1: C31_A1 C32_A1 C33_A1 C34_A1 C35_A1 C36_A1 C37_A1 C38_A1 C39_A1 C40_A1 J7_A1 J8_A1 L1_A1 L2_A1 L3_A1 L4_A1 L5_A1 L6_A1 L7_A1 L8_A1 L9_A1 R36_A1 R37_A1 R38_A1 R41_A1 SH1_A1 U5_A1 U6_A1
channel class analog_channel: A1 A2 A3 A4 A5 A6 A7 A8
channel class "Level Shifter": LS1 LS2 LS3 LS4
channel class main: M1 M2
differential pair CH3_M2: +CH3_M2_P -CH3_M2_N
differential pair CH3_M1: +CH3_M1_P -CH3_M1_N
differential pair CH2_M2: +CH2_M2_P -CH2_M2_N
differential pair CH2_M1: +CH2_M1_P -CH2_M1_N
differential pair CH1_M2: +CH1_M2_P -CH1_M2_N
differential pair CH1_M1: +CH1_M1_P -CH1_M1_N
differential pair CH0_M2: +CH0_M2_P -CH0_M2_N
differential pair CH0_M1: +CH0_M1_P -CH0_M1_N

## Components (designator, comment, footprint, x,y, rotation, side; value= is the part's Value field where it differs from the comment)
C1_M1 "680pF 50V" C0402 60.141,68.898 r180 bottom (schematic designator C1)
C1_M2 "680pF 50V" C0402 60.193,32.616 r180 bottom (schematic designator C1)
C2_M1 "39pF 50V" C0402 63.918,68.39 r180 bottom (schematic designator C2)
C2_M2 "39pF 50V" C0402 64.664,33.306 r180 bottom (schematic designator C2)
C3_M1 "39pF 50V" C0402 63.156,63.564 r180 bottom (schematic designator C3)
C3_M2 "39pF 50V" C0402 63.902,28.48 r180 bottom (schematic designator C3)
C4_M1 "1uF 25V" C0402 53.552,67.247 r180 bottom (schematic designator C4)
C4_M2 "1uF 25V" C0402 53.604,30.965 r180 bottom (schematic designator C4)
C5_M1 "1uF 25V" C0402 57.578,65.126 r270 bottom (schematic designator C5)
C5_M2 "1uF 25V" C0402 57.63,28.845 r270 bottom (schematic designator C5)
C6_M1 "1uF 25V" C0402 55.546,63.841 r270 bottom (schematic designator C6)
C6_M2 "1uF 25V" C0402 55.598,27.559 r270 bottom (schematic designator C6)
C7_M1 "10uF 10V" C0402 50.523,67.564 r0 top (schematic designator C7)
C7_M2 "10uF 10V" C0402 50.777,31.115 r0 top (schematic designator C7)
C8_M1 "10uF 10V" C0402 53.006,64.999 r270 bottom (schematic designator C8)
C8_M2 "10uF 10V" C0402 53.058,28.718 r270 bottom (schematic designator C8)
C9_M1 "10uF 10V" C0402 59.991,63.31 r0 bottom (schematic designator C9)
C9_M2 "10uF 10V" C0402 60.043,27.028 r0 bottom (schematic designator C9)
C10_M1 "0.1uF 50V" C0402 50.523,66.548 r0 top (schematic designator C10)
C10_M2 "0.1uF 50V" C0402 50.762,30.068 r0 top (schematic designator C10)
C11_M1 "0.1uF 50V" C0402 53.552,68.644 r180 bottom (schematic designator C11)
C11_M2 "0.1uF 50V" C0402 53.604,32.362 r180 bottom (schematic designator C11)
C12_M1 "0.1uF 50V" C0402 58.34,70.93 r180 bottom (schematic designator C12)
C12_M2 "0.1uF 50V" C0402 58.392,34.648 r180 bottom (schematic designator C12)
C13 "10uF 25V" C0603 84.644,84.9 r0 top
C14 "10nF 25V" C0402 84.544,82.106 r0 top
C15 "10nF 25V" C0402 82.479,47.689 r90 top
C16 "22uF 16V" C0603 75.494,43.837 r90 top
C17 "22uF 16V" C0603 75.048,47.712 r0 top
C18 "10nF 25V" C0402 74.224,43.498 r90 top
C19 "10nF 25V" C0402 81.082,47.689 r90 top
C20 "10uF 25V" C0603 78.477,49.49 r0 top
C21 "NA" C0402 81.082,45.068 r270 top
C22 "10nF 25V" C0402 82.495,38.915 r90 top
C23 "22uF 16V" C0603 74.24,34.724 r90 top
C24 "10nF 25V" C0402 81.098,38.915 r90 top
C25 "10nF 25V" C0402 77.161,34.555 r90 top
C26 "10uF 25V" C0603 75.064,38.938 r0 top
C27 "22uF 16V" C0603 78.493,40.716 r0 top
C28 "NA" C0402 81.098,36.294 r270 top
C29_LS1 "0.1uF 50V" C0402 75.661,17.943 r180 top (schematic designator C29)
C29_LS2 "0.1uF 50V" C0402 71.574,19.467 r180 top (schematic designator C29)
C29_LS3 "0.1uF 50V" C0402 86.344,15.911 r180 bottom (schematic designator C29)
C29_LS4 "0.1uF 50V" C0402 79.702,14.73 r90 bottom (schematic designator C29)
C30_LS1 "0.1uF 50V" C0402 75.661,18.959 r180 top (schematic designator C30)
C30_LS2 "0.1uF 50V" C0402 71.574,18.324 r180 top (schematic designator C30)
C30_LS3 "0.1uF 50V" C0402 84.782,15.111 r90 bottom (schematic designator C30)
C30_LS4 "0.1uF 50V" C0402 80.629,16.292 r180 bottom (schematic designator C30)
C31_A1 "1uF 25V" C0402 22.629,80.391 r180 top (schematic designator C31)
C31_A2 "1uF 25V" C0402 22.629,71.264 r180 top (schematic designator C31)
C31_A3 "1uF 25V" C0402 22.629,62.264 r180 top (schematic designator C31)
C31_A4 "1uF 25V" C0402 22.629,53.264 r180 top (schematic designator C31)
C31_A5 "1uF 25V" C0402 22.629,44.264 r180 top (schematic designator C31)
C31_A6 "1uF 25V" C0402 22.629,35.264 r180 top (schematic designator C31)
C31_A7 "1uF 25V" C0402 22.629,26.289 r180 top (schematic designator C31)
C31_A8 "1uF 25V" C0402 22.629,17.272 r180 top (schematic designator C31)
C32_A1 "1uF 25V" C0402 27.432,78.232 r180 top (schematic designator C32)
C32_A2 "1uF 25V" C0402 27.432,69.105 r180 top (schematic designator C32)
C32_A3 "1uF 25V" C0402 27.432,60.105 r180 top (schematic designator C32)
C32_A4 "1uF 25V" C0402 27.432,51.105 r180 top (schematic designator C32)
C32_A5 "1uF 25V" C0402 27.432,42.105 r180 top (schematic designator C32)
C32_A6 "1uF 25V" C0402 27.432,33.105 r180 top (schematic designator C32)
C32_A7 "1uF 25V" C0402 27.432,24.13 r180 top (schematic designator C32)
C32_A8 "1uF 25V" C0402 27.432,15.113 r180 top (schematic designator C32)
C33_A1 "16pF 50V" C0402 18.97,79.131 r270 top (schematic designator C33)
C33_A2 "16pF 50V" C0402 18.97,70.004 r270 top (schematic designator C33)
C33_A3 "16pF 50V" C0402 18.97,61.004 r270 top (schematic designator C33)
C33_A4 "16pF 50V" C0402 18.97,52.004 r270 top (schematic designator C33)
C33_A5 "16pF 50V" C0402 18.97,43.004 r270 top (schematic designator C33)
C33_A6 "16pF 50V" C0402 18.97,34.004 r270 top (schematic designator C33)
C33_A7 "16pF 50V" C0402 18.97,25.029 r270 top (schematic designator C33)
C33_A8 "16pF 50V" C0402 18.97,16.012 r270 top (schematic designator C33)
C34_A1 "11pF 50V" C0402 16.811,79.027 r270 top (schematic designator C34)
C34_A2 "11pF 50V" C0402 16.811,69.9 r270 top (schematic designator C34)
C34_A3 "11pF 50V" C0402 16.811,60.9 r270 top (schematic designator C34)
C34_A4 "11pF 50V" C0402 16.811,51.9 r270 top (schematic designator C34)
C34_A5 "11pF 50V" C0402 16.811,42.9 r270 top (schematic designator C34)
C34_A6 "11pF 50V" C0402 16.811,33.9 r270 top (schematic designator C34)
C34_A7 "11pF 50V" C0402 16.811,24.925 r270 top (schematic designator C34)
C34_A8 "11pF 50V" C0402 16.811,15.908 r270 top (schematic designator C34)
C35_A1 "10pF 50V" C0402 14.779,79.027 r270 top (schematic designator C35)
C35_A2 "10pF 50V" C0402 14.779,69.9 r270 top (schematic designator C35)
C35_A3 "10pF 50V" C0402 14.779,60.9 r270 top (schematic designator C35)
C35_A4 "10pF 50V" C0402 14.779,51.9 r270 top (schematic designator C35)
C35_A5 "10pF 50V" C0402 14.779,42.9 r270 top (schematic designator C35)
C35_A6 "10pF 50V" C0402 14.779,33.9 r270 top (schematic designator C35)
C35_A7 "10pF 50V" C0402 14.779,24.925 r270 top (schematic designator C35)
C35_A8 "10pF 50V" C0402 14.779,15.908 r270 top (schematic designator C35)
C36_A1 "13pF 50V" C0402 12.874,79.004 r270 top (schematic designator C36)
C36_A2 "13pF 50V" C0402 12.874,69.877 r270 top (schematic designator C36)
C36_A3 "13pF 50V" C0402 12.874,60.877 r270 top (schematic designator C36)
C36_A4 "13pF 50V" C0402 12.874,51.877 r270 top (schematic designator C36)
C36_A5 "13pF 50V" C0402 12.874,42.877 r270 top (schematic designator C36)
C36_A6 "13pF 50V" C0402 12.874,33.877 r270 top (schematic designator C36)
C36_A7 "13pF 50V" C0402 12.874,24.902 r270 top (schematic designator C36)
C36_A8 "13pF 50V" C0402 12.874,15.885 r270 top (schematic designator C36)
C37_A1 "1uF 25V" C0402 25.527,79.337 r90 bottom (schematic designator C37)
C37_A2 "1uF 25V" C0402 25.527,70.21 r90 bottom (schematic designator C37)
C37_A3 "1uF 25V" C0402 25.527,61.21 r90 bottom (schematic designator C37)
C37_A4 "1uF 25V" C0402 25.527,52.21 r90 bottom (schematic designator C37)
C37_A5 "1uF 25V" C0402 25.527,43.21 r90 bottom (schematic designator C37)
C37_A6 "1uF 25V" C0402 25.527,34.21 r90 bottom (schematic designator C37)
C37_A7 "1uF 25V" C0402 25.527,25.235 r90 bottom (schematic designator C37)
C37_A8 "1uF 25V" C0402 25.527,16.218 r90 bottom (schematic designator C37)
C38_A1 "0.1uF 50V" C0402 26.543,79.352 r90 bottom (schematic designator C38)
C38_A2 "0.1uF 50V" C0402 26.543,70.225 r90 bottom (schematic designator C38)
C38_A3 "0.1uF 50V" C0402 26.543,61.225 r90 bottom (schematic designator C38)
C38_A4 "0.1uF 50V" C0402 26.543,52.225 r90 bottom (schematic designator C38)
C38_A5 "0.1uF 50V" C0402 26.543,43.225 r90 bottom (schematic designator C38)
C38_A6 "0.1uF 50V" C0402 26.543,34.225 r90 bottom (schematic designator C38)
C38_A7 "0.1uF 50V" C0402 26.543,25.25 r90 bottom (schematic designator C38)
C38_A8 "0.1uF 50V" C0402 26.543,16.233 r90 bottom (schematic designator C38)
C39_A1 "0.1uF 50V" C0402 39.751,77.059 r270 bottom (schematic designator C39)
C39_A2 "0.1uF 50V" C0402 39.751,67.932 r270 bottom (schematic designator C39)
C39_A3 "0.1uF 50V" C0402 39.751,58.932 r270 bottom (schematic designator C39)
C39_A4 "0.1uF 50V" C0402 39.751,49.932 r270 bottom (schematic designator C39)
C39_A5 "0.1uF 50V" C0402 39.751,40.932 r270 bottom (schematic designator C39)
C39_A6 "0.1uF 50V" C0402 39.751,31.932 r270 bottom (schematic designator C39)
C39_A7 "0.1uF 50V" C0402 39.751,22.957 r270 bottom (schematic designator C39)
C39_A8 "0.1uF 50V" C0402 39.751,13.94 r270 bottom (schematic designator C39)
C40_A1 "1uF 25V" C0402 39.243,75.535 r0 bottom (schematic designator C40)
C40_A2 "1uF 25V" C0402 39.243,66.408 r0 bottom (schematic designator C40)
C40_A3 "1uF 25V" C0402 39.243,57.408 r0 bottom (schematic designator C40)
C40_A4 "1uF 25V" C0402 39.243,48.408 r0 bottom (schematic designator C40)
C40_A5 "1uF 25V" C0402 39.243,39.408 r0 bottom (schematic designator C40)
C40_A6 "1uF 25V" C0402 39.243,30.408 r0 bottom (schematic designator C40)
C40_A7 "1uF 25V" C0402 39.243,21.433 r0 bottom (schematic designator C40)
C40_A8 "1uF 25V" C0402 39.243,12.416 r0 bottom (schematic designator C40)
C41_M1 "0.1uF 50V" C0402 50.421,80.391 r180 bottom (schematic designator C41)
C41_M2 "0.1uF 50V" C0402 50.421,45.466 r180 bottom (schematic designator C41)
C42_M1 "0.1uF 50V" C0402 50.421,81.534 r180 bottom (schematic designator C42)
C42_M2 "0.1uF 50V" C0402 50.421,44.323 r180 bottom (schematic designator C42)
C43_M1 "10uF 10V" C0402 50.421,79.248 r180 bottom (schematic designator C43)
C43_M2 "10uF 10V" C0402 50.421,43.18 r180 bottom (schematic designator C43)
C57_M1 "0.1uF 50V" C0402 50.421,72.644 r180 bottom (schematic designator C57)
C57_M2 "0.1uF 50V" C0402 50.421,36.576 r180 bottom (schematic designator C57)
C58_M1 "0.1uF 50V" C0402 50.421,71.501 r180 bottom (schematic designator C58)
C58_M2 "0.1uF 50V" C0402 50.421,35.433 r180 bottom (schematic designator C58)
C59_M1 "10uF 10V" C0402 50.421,70.358 r180 bottom (schematic designator C59)
C59_M2 "10uF 10V" C0402 50.421,34.29 r180 bottom (schematic designator C59)
C60_M1 "0.1uF 50V" C0402 50.421,63.373 r180 bottom (schematic designator C60)
C60_M2 "0.1uF 50V" C0402 50.421,27.089 r180 bottom (schematic designator C60)
C61_M1 "0.1uF 50V" C0402 50.421,62.23 r180 bottom (schematic designator C61)
C61_M2 "0.1uF 50V" C0402 50.421,25.946 r180 bottom (schematic designator C61)
C62_M1 "10uF 10V" C0402 50.421,61.087 r180 bottom (schematic designator C62)
C62_M2 "10uF 10V" C0402 50.421,24.803 r180 bottom (schematic designator C62)
C63_M1 "0.1uF 50V" C0402 50.421,54.483 r180 bottom (schematic designator C63)
C63_M2 "0.1uF 50V" C0402 50.421,18.326 r180 bottom (schematic designator C63)
C64_M1 "0.1uF 50V" C0402 50.421,53.34 r180 bottom (schematic designator C64)
C64_M2 "0.1uF 50V" C0402 50.421,17.183 r180 bottom (schematic designator C64)
C65_M1 "10uF 10V" C0402 50.421,52.197 r180 bottom (schematic designator C65)
C65_M2 "10uF 10V" C0402 50.421,16.04 r180 bottom (schematic designator C65)
F1 "PTC 24V / 1.5A" 1812_F 61.468,14.794 r90 top
F2 "PTC 24V / 1.5A" 1812_F 65.151,14.794 r90 top
F3 "PTC 24V / 1.5A" 1812_F 57.785,14.794 r270 top
FB1_M1 "BLM18EG221SN1D" FB0603 57.389,63.437 r180 bottom (schematic designator FB1)
FB1_M2 "BLM18EG221SN1D" FB0603 57.441,27.155 r180 bottom (schematic designator FB1)
FB2 "BLM18EG221SN1D" FB0603 81.782,49.49 r180 top
FB3 "BLM18EG221SN1D" FB0603 75.048,45.553 r180 top
FB4 "BLM18EG221SN1D" FB0603 81.798,40.716 r180 top
FB5 "BLM18EG221SN1D" FB0603 75.064,36.779 r180 top
FID1 "Fiducial" FIDUCIAL 72.644,85.408 r90 top
FID2 "Fiducial" FIDUCIAL 94.107,13.145 r90 top
FID3 "Fiducial" FIDUCIAL 11.049,7.43 r90 top
FID4 "Fiducial" FIDUCIAL 72.771,85.408 r90 bottom
FID5 "Fiducial" FIDUCIAL 94.234,13.145 r90 bottom
FID6 "Fiducial" FIDUCIAL 11.303,7.43 r90 bottom
H1 "Hole 3mm" "HOLE 3MM" 97.762,78.509 r0 top
H2 "Hole 3mm" "HOLE 3MM" 4.762,84.509 r0 top
H3 "Hole 3mm" "HOLE 3MM" 97.762,15.009 r0 top
H4 "Hole 3mm" "HOLE 3MM" 4.762,8.009 r0 top
J1 "1053141204" CON_1053141204 88.559,85.027 r90 top
J2 "5767096-1" MICTOR-38_PIN 88.326,68.776 r90 top
J3 "90131-0770" HEADER_10X2 67.421,76.518 r270 top
J4 "90131-0770" HEADER_10X2 82.153,76.391 r270 top
J5 "90131-0770" HEADER_10X2 74.914,76.518 r270 top
J6 "10018784-10201TLF" PCIE_8LANE_EDGE 71.379,6.521 r0 top locked
J7_A1 "SMA-J-P-H-RA-TH1" CONN_SMA-J-P-H-RA-TH1_SAI 4.572,78.613 r90 top (schematic designator J7)
J7_A2 "SMA-J-P-H-RA-TH1" CONN_SMA-J-P-H-RA-TH1_SAI 4.572,69.486 r270 bottom (schematic designator J7)
J7_A3 "SMA-J-P-H-RA-TH1" CONN_SMA-J-P-H-RA-TH1_SAI 4.572,60.486 r90 top (schematic designator J7)
J7_A4 "SMA-J-P-H-RA-TH1" CONN_SMA-J-P-H-RA-TH1_SAI 4.572,51.486 r270 bottom (schematic designator J7)
J7_A5 "SMA-J-P-H-RA-TH1" CONN_SMA-J-P-H-RA-TH1_SAI 4.572,42.486 r90 top (schematic designator J7)
J7_A6 "SMA-J-P-H-RA-TH1" CONN_SMA-J-P-H-RA-TH1_SAI 4.572,33.486 r270 bottom (schematic designator J7)
J7_A7 "SMA-J-P-H-RA-TH1" CONN_SMA-J-P-H-RA-TH1_SAI 4.572,24.511 r90 top (schematic designator J7)
J7_A8 "SMA-J-P-H-RA-TH1" CONN_SMA-J-P-H-RA-TH1_SAI 4.572,15.494 r270 bottom (schematic designator J7)
J8_A1 "MMCX-J-P-H-ST-TH1" SAMTEC_MMCX-J-P-H-ST-TH1 38.227,81.407 r270 top (schematic designator J8)
J8_A2 "MMCX-J-P-H-ST-TH1" SAMTEC_MMCX-J-P-H-ST-TH1 38.227,72.28 r270 top (schematic designator J8)
J8_A3 "MMCX-J-P-H-ST-TH1" SAMTEC_MMCX-J-P-H-ST-TH1 38.227,63.28 r270 top (schematic designator J8)
J8_A4 "MMCX-J-P-H-ST-TH1" SAMTEC_MMCX-J-P-H-ST-TH1 38.227,54.28 r270 top (schematic designator J8)
J8_A5 "MMCX-J-P-H-ST-TH1" SAMTEC_MMCX-J-P-H-ST-TH1 38.227,45.28 r270 top (schematic designator J8)
J8_A6 "MMCX-J-P-H-ST-TH1" SAMTEC_MMCX-J-P-H-ST-TH1 38.227,36.28 r270 top (schematic designator J8)
J8_A7 "MMCX-J-P-H-ST-TH1" SAMTEC_MMCX-J-P-H-ST-TH1 38.227,27.305 r270 top (schematic designator J8)
J8_A8 "MMCX-J-P-H-ST-TH1" SAMTEC_MMCX-J-P-H-ST-TH1 38.227,18.288 r270 top (schematic designator J8)
L1_A1 "Inductor" 0402-A 17.954,80.401 r180 top value=56nH (schematic designator L1)
L1_A2 "Inductor" 0402-A 17.954,71.274 r180 top value=56nH (schematic designator L1)
L1_A3 "Inductor" 0402-A 17.954,62.274 r180 top value=56nH (schematic designator L1)
L1_A4 "Inductor" 0402-A 17.954,53.274 r180 top value=56nH (schematic designator L1)
L1_A5 "Inductor" 0402-A 17.954,44.274 r180 top value=56nH (schematic designator L1)
L1_A6 "Inductor" 0402-A 17.954,35.274 r180 top value=56nH (schematic designator L1)
L1_A7 "Inductor" 0402-A 17.954,26.299 r180 top value=56nH (schematic designator L1)
L1_A8 "Inductor" 0402-A 17.954,17.282 r180 top value=56nH (schematic designator L1)
L2_A1 "Inductor" 0402-A 20.105,80.402 r180 top value=43nH (schematic designator L2)
L2_A2 "Inductor" 0402-A 20.105,71.275 r180 top value=43nH (schematic designator L2)
L2_A3 "Inductor" 0402-A 20.105,62.275 r180 top value=43nH (schematic designator L2)
L2_A4 "Inductor" 0402-A 20.105,53.275 r180 top value=43nH (schematic designator L2)
L2_A5 "Inductor" 0402-A 20.105,44.275 r180 top value=43nH (schematic designator L2)
L2_A6 "Inductor" 0402-A 20.105,35.275 r180 top value=43nH (schematic designator L2)
L2_A7 "Inductor" 0402-A 20.105,26.3 r180 top value=43nH (schematic designator L2)
L2_A8 "Inductor" 0402-A 20.105,17.283 r180 top value=43nH (schematic designator L2)
L3_A1 "Inductor" 0402-A 15.795,80.401 r180 top value=43nH (schematic designator L3)
L3_A2 "Inductor" 0402-A 15.795,71.274 r180 top value=43nH (schematic designator L3)
L3_A3 "Inductor" 0402-A 15.795,62.274 r180 top value=43nH (schematic designator L3)
L3_A4 "Inductor" 0402-A 15.795,53.274 r180 top value=43nH (schematic designator L3)
L3_A5 "Inductor" 0402-A 15.795,44.274 r180 top value=43nH (schematic designator L3)
L3_A6 "Inductor" 0402-A 15.795,35.274 r180 top value=43nH (schematic designator L3)
L3_A7 "Inductor" 0402-A 15.795,26.299 r180 top value=43nH (schematic designator L3)
L3_A8 "Inductor" 0402-A 15.795,17.282 r180 top value=43nH (schematic designator L3)
L4_A1 "Inductor" 0402-A 13.763,80.401 r180 top value=47nH (schematic designator L4)
L4_A2 "Inductor" 0402-A 13.763,71.274 r180 top value=47nH (schematic designator L4)
L4_A3 "Inductor" 0402-A 13.763,62.274 r180 top value=47nH (schematic designator L4)
L4_A4 "Inductor" 0402-A 13.763,53.274 r180 top value=47nH (schematic designator L4)
L4_A5 "Inductor" 0402-A 13.763,44.274 r180 top value=47nH (schematic designator L4)
L4_A6 "Inductor" 0402-A 13.763,35.274 r180 top value=47nH (schematic designator L4)
L4_A7 "Inductor" 0402-A 13.763,26.299 r180 top value=47nH (schematic designator L4)
L4_A8 "Inductor" 0402-A 13.763,17.282 r180 top value=47nH (schematic designator L4)
L5_A1 "Inductor" 0402-A 11.604,80.401 r180 top value=33nH (schematic designator L5)
L5_A2 "Inductor" 0402-A 11.604,71.274 r180 top value=33nH (schematic designator L5)
L5_A3 "Inductor" 0402-A 11.604,62.274 r180 top value=33nH (schematic designator L5)
L5_A4 "Inductor" 0402-A 11.604,53.274 r180 top value=33nH (schematic designator L5)
L5_A5 "Inductor" 0402-A 11.604,44.274 r180 top value=33nH (schematic designator L5)
L5_A6 "Inductor" 0402-A 11.604,35.274 r180 top value=33nH (schematic designator L5)
L5_A7 "Inductor" 0402-A 11.604,26.299 r180 top value=33nH (schematic designator L5)
L5_A8 "Inductor" 0402-A 11.604,17.282 r180 top value=33nH (schematic designator L5)
L6_A1 "Inductor" 0402-A 16.811,76.853 r270 top value=24nH (schematic designator L6)
L6_A2 "Inductor" 0402-A 16.811,67.726 r270 top value=24nH (schematic designator L6)
L6_A3 "Inductor" 0402-A 16.811,58.726 r270 top value=24nH (schematic designator L6)
L6_A4 "Inductor" 0402-A 16.811,49.726 r270 top value=24nH (schematic designator L6)
L6_A5 "Inductor" 0402-A 16.811,40.726 r270 top value=24nH (schematic designator L6)
L6_A6 "Inductor" 0402-A 16.811,31.726 r270 top value=24nH (schematic designator L6)
L6_A7 "Inductor" 0402-A 16.811,22.751 r270 top value=24nH (schematic designator L6)
L6_A8 "Inductor" 0402-A 16.811,13.734 r270 top value=24nH (schematic designator L6)
L7_A1 "Inductor" 0402-A 14.779,76.853 r270 top value=33nH (schematic designator L7)
L7_A2 "Inductor" 0402-A 14.779,67.726 r270 top value=33nH (schematic designator L7)
L7_A3 "Inductor" 0402-A 14.779,58.726 r270 top value=33nH (schematic designator L7)
L7_A4 "Inductor" 0402-A 14.779,49.726 r270 top value=33nH (schematic designator L7)
L7_A5 "Inductor" 0402-A 14.779,40.726 r270 top value=33nH (schematic designator L7)
L7_A6 "Inductor" 0402-A 14.779,31.726 r270 top value=33nH (schematic designator L7)
L7_A7 "Inductor" 0402-A 14.779,22.751 r270 top value=33nH (schematic designator L7)
L7_A8 "Inductor" 0402-A 14.779,13.734 r270 top value=33nH (schematic designator L7)
L8_A1 "Inductor" 0402-A 12.874,76.718 r270 top value=15nH (schematic designator L8)
L8_A2 "Inductor" 0402-A 12.874,67.591 r270 top value=15nH (schematic designator L8)
L8_A3 "Inductor" 0402-A 12.874,58.591 r270 top value=15nH (schematic designator L8)
L8_A4 "Inductor" 0402-A 12.874,49.591 r270 top value=15nH (schematic designator L8)
L8_A5 "Inductor" 0402-A 12.874,40.591 r270 top value=15nH (schematic designator L8)
L8_A6 "Inductor" 0402-A 12.874,31.591 r270 top value=15nH (schematic designator L8)
L8_A7 "Inductor" 0402-A 12.874,22.616 r270 top value=15nH (schematic designator L8)
L8_A8 "Inductor" 0402-A 12.874,13.599 r270 top value=15nH (schematic designator L8)
L9_A1 "Inductor" 0402-A 18.97,76.853 r270 top value=3.9nH (schematic designator L9)
L9_A2 "Inductor" 0402-A 18.97,67.726 r270 top value=3.9nH (schematic designator L9)
L9_A3 "Inductor" 0402-A 18.97,58.726 r270 top value=3.9nH (schematic designator L9)
L9_A4 "Inductor" 0402-A 18.97,49.726 r270 top value=3.9nH (schematic designator L9)
L9_A5 "Inductor" 0402-A 18.97,40.726 r270 top value=3.9nH (schematic designator L9)
L9_A6 "Inductor" 0402-A 18.97,31.726 r270 top value=3.9nH (schematic designator L9)
L9_A7 "Inductor" 0402-A 18.97,22.751 r270 top value=3.9nH (schematic designator L9)
L9_A8 "Inductor" 0402-A 18.97,13.734 r270 top value=3.9nH (schematic designator L9)
LD1 "APT1608SGC" LED_0603_GREEN 70.088,47.638 r90 top
LD2 "APT1608SGC" LED_0603_GREEN 70.104,38.864 r90 top
Lp1 "NR6028T100M" IND6X6_H3 90.034,42.228 r180 top
R1_M1 "6.8K" R0402 59.991,64.707 r0 bottom (schematic designator R1)
R1_M2 "6.8K" R0402 60.043,28.425 r0 bottom (schematic designator R1)
R2_M1 "0R" R0402 60.118,69.914 r180 bottom (schematic designator R2)
R2_M2 "0R" R0402 60.17,33.632 r180 bottom (schematic designator R2)
R3_M1 "10K" R0402 87.884,19.073 r270 top (schematic designator R3)
R3_M2 "10K" R0402 82.169,19.177 r270 top (schematic designator R3)
R4_M1 "10K" R0402 86.868,19.073 r270 top (schematic designator R4)
R4_M2 "10K" R0402 81.153,19.177 r270 top (schematic designator R4)
R5_M1 "10K" R0402 85.852,19.073 r270 top (schematic designator R5)
R5_M2 "10K" R0402 80.137,19.177 r270 top (schematic designator R5)
R6_M1 "10K" R0402 84.836,19.073 r270 top (schematic designator R6)
R6_M2 "10K" R0402 79.121,19.177 r270 top (schematic designator R6)
R7_M1 "NA" R0402 53.044,63.31 r180 bottom (schematic designator R7)
R7_M2 "NA" R0402 53.096,27.028 r180 bottom (schematic designator R7)
R8_M1 "0R" R0402 60.626,66.396 r270 bottom (schematic designator R8)
R8_M2 "0R" R0402 60.678,30.115 r270 bottom (schematic designator R8)
R9_M1 "0R" R0402 54.53,63.841 r270 bottom (schematic designator R9)
R9_M2 "0R" R0402 54.582,27.559 r270 bottom (schematic designator R9)
R10_M1 "NA" R0402 60.08,67.882 r0 bottom (schematic designator R10)
R10_M2 "NA" R0402 60.132,31.6 r0 bottom (schematic designator R10)
R11_M1 "10K" R0402 56.054,70.168 r90 bottom (schematic designator R11)
R11_M2 "10K" R0402 56.106,33.886 r90 bottom (schematic designator R11)
R12_M1 "10K" R0402 55.038,70.168 r90 bottom (schematic designator R12)
R12_M2 "10K" R0402 55.09,33.886 r90 bottom (schematic designator R12)
R13_M1 "10K" R0402 54.022,70.168 r90 bottom (schematic designator R13)
R13_M2 "10K" R0402 54.074,33.886 r90 bottom (schematic designator R13)
R14_M1 "10K" R0402 53.006,70.168 r90 bottom (schematic designator R14)
R14_M2 "10K" R0402 53.058,33.886 r90 bottom (schematic designator R14)
R15_M1 "0R" R0805 46.96,51.498 r0 bottom (schematic designator R15)
R15_M2 "0R" R0805 46.006,15.373 r0 bottom (schematic designator R15)
R16_M1 "0R" R0805 46.006,64.071 r0 bottom (schematic designator R16)
R16_M2 "0R" R0805 46.006,27.692 r0 bottom (schematic designator R16)
R17_M1 "0R" R0805 46.006,73.215 r0 bottom (schematic designator R17)
R17_M2 "0R" R0805 46.006,37.179 r0 bottom (schematic designator R17)
R18_M1 "0R" R0805 46.006,78.549 r0 bottom (schematic designator R18)
R18_M2 "0R" R0805 46.006,42.513 r0 bottom (schematic designator R18)
R19_M1 "0R" R0805 46.96,55.054 r0 bottom (schematic designator R19)
R19_M2 "0R" R0805 46.96,18.929 r0 bottom (schematic designator R19)
R20_M1 "0R" R0805 46.006,62.293 r0 bottom (schematic designator R20)
R20_M2 "0R" R0805 46.006,25.914 r0 bottom (schematic designator R20)
R21_M1 "0R" R0805 46.006,69.659 r0 bottom (schematic designator R21)
R21_M2 "0R" R0805 46.006,33.623 r0 bottom (schematic designator R21)
R22_M1 "0R" R0805 46.006,80.327 r0 bottom (schematic designator R22)
R22_M2 "0R" R0805 46.006,44.291 r0 bottom (schematic designator R22)
R23_M1 "0R" R0805 46.96,53.276 r0 bottom (schematic designator R23)
R23_M2 "0R" R0805 46.96,17.151 r0 bottom (schematic designator R23)
R24_M1 "0R" R0805 46.006,60.642 r0 bottom (schematic designator R24)
R24_M2 "0R" R0805 46.006,24.263 r0 bottom (schematic designator R24)
R25_M1 "0R" R0805 46.006,71.437 r0 bottom (schematic designator R25)
R25_M2 "0R" R0805 46.006,35.401 r0 bottom (schematic designator R25)
R26_M1 "0R" R0805 46.006,82.105 r0 bottom (schematic designator R26)
R26_M2 "0R" R0805 46.006,46.069 r0 bottom (schematic designator R26)
R27 "124K" R0402 78.415,43.544 r270 top
R28 "1K" R0402 70.033,45.337 r270 top
R29 "39.2K" R0402 79.431,43.498 r90 top
R30 "124K" R0402 78.431,34.77 r270 top
R31 "1K" R0402 70.049,36.563 r270 top
R32 "100K" R0402 79.447,34.724 r90 top
R33 "0R" R0402 53.721,47.879 r90 top
R34_LS1 "100K" R0402 73.86,16.673 r270 top (schematic designator R34)
R34_LS2 "100K" R0402 69.542,16.546 r90 top (schematic designator R34)
R34_LS3 "100K" R0402 83.639,16.673 r90 top (schematic designator R34)
R34_LS4 "100K" R0402 78.432,16.546 r90 top (schematic designator R34)
R35_LS1 "NA" R0402 73.86,14.514 r90 top (schematic designator R35)
R35_LS2 "NA" R0402 69.542,14.349 r90 top (schematic designator R35)
R35_LS3 "NA" R0402 83.639,14.491 r90 top (schematic designator R35)
R35_LS4 "NA" R0402 78.432,14.387 r90 top (schematic designator R35)
R36_A1 "34.8R" R0402 32.109,78.222 r0 top (schematic designator R36)
R36_A2 "34.8R" R0402 32.109,69.095 r0 top (schematic designator R36)
R36_A3 "34.8R" r0402 32.109,60.095 r0 top (schematic designator R36)
R36_A4 "34.8R" r0402 32.109,51.095 r0 top (schematic designator R36)
R36_A5 "34.8R" R0402 32.109,42.095 r0 top (schematic designator R36)
R36_A6 "34.8R" R0402 32.109,33.095 r0 top (schematic designator R36)
R36_A7 "34.8R" r0402 32.109,24.12 r0 top (schematic designator R36)
R36_A8 "34.8R" r0402 32.109,15.103 r0 top (schematic designator R36)
R37_A1 "34.8R" R0402 29.273,78.221 r0 top (schematic designator R37)
R37_A2 "34.8R" R0402 29.273,69.094 r0 top (schematic designator R37)
R37_A3 "34.8R" r0402 29.273,60.094 r0 top (schematic designator R37)
R37_A4 "34.8R" r0402 29.273,51.094 r0 top (schematic designator R37)
R37_A5 "34.8R" R0402 29.273,42.094 r0 top (schematic designator R37)
R37_A6 "34.8R" R0402 29.273,33.094 r0 top (schematic designator R37)
R37_A7 "34.8R" r0402 29.273,24.119 r0 top (schematic designator R37)
R37_A8 "34.8R" r0402 29.273,15.102 r0 top (schematic designator R37)
R38_A1 "18.2R" R0402 30.734,77.762 r270 top (schematic designator R38)
R38_A2 "18.2R" R0402 30.734,68.635 r270 top (schematic designator R38)
R38_A3 "18.2R" r0402 30.734,59.635 r270 top (schematic designator R38)
R38_A4 "18.2R" r0402 30.734,50.635 r270 top (schematic designator R38)
R38_A5 "18.2R" R0402 30.734,41.635 r270 top (schematic designator R38)
R38_A6 "18.2R" R0402 30.734,32.635 r270 top (schematic designator R38)
R38_A7 "18.2R" r0402 30.734,23.66 r270 top (schematic designator R38)
R38_A8 "18.2R" r0402 30.734,14.643 r270 top (schematic designator R38)
R39_M1 "49.9R" R0402 49.736,78.321 r90 top (schematic designator R39)
R39_M2 "49.9R" R0402 49.736,42.253 r90 top (schematic designator R39)
R40_M1 "49.9R" R0402 49.736,82.4 r90 top (schematic designator R40)
R40_M2 "49.9R" R0402 49.736,46.332 r90 top (schematic designator R40)
R41_A1 "NA" R0402 32.639,79.779 r270 top (schematic designator R41)
R41_A2 "NA" R0402 32.639,70.652 r270 top (schematic designator R41)
R41_A3 "NA" r0402 32.639,61.652 r270 top (schematic designator R41)
R41_A4 "NA" r0402 32.639,52.652 r270 top (schematic designator R41)
R41_A5 "NA" R0402 32.639,43.652 r270 top (schematic designator R41)
R41_A6 "NA" R0402 32.639,34.652 r270 top (schematic designator R41)
R41_A7 "NA" r0402 32.639,25.677 r270 top (schematic designator R41)
R41_A8 "NA" r0402 32.639,16.66 r270 top (schematic designator R41)
R50_M1 "49.9R" R0402 49.736,69.431 r90 top (schematic designator R50)
R50_M2 "49.9R" R0402 49.736,33.363 r90 top (schematic designator R50)
R51_M1 "49.9R" R0402 49.736,73.51 r90 top (schematic designator R51)
R51_M2 "49.9R" R0402 49.736,37.442 r90 top (schematic designator R51)
R52_M1 "49.9R" R0402 49.736,64.3 r270 top (schematic designator R52)
R52_M2 "49.9R" R0402 49.736,23.838 r90 top (schematic designator R52)
R53_M1 "49.9R" R0402 49.736,60.221 r270 top (schematic designator R53)
R53_M2 "49.9R" R0402 49.736,27.917 r90 top (schematic designator R53)
R54_M1 "49.9R" R0402 49.736,55.41 r270 top (schematic designator R54)
R54_M2 "49.9R" R0402 49.736,19.215 r270 top (schematic designator R54)
R55_M1 "49.9R" R0402 49.736,51.331 r270 top (schematic designator R55)
R55_M2 "49.9R" R0402 49.736,15.136 r270 top (schematic designator R55)
SH1_A1 "RF_SHIELD" RF_Sh 22.034,78.613 r0 top (schematic designator SH1)
SH1_A2 "RF_SHIELD" RF_Sh 22.034,69.469 r0 top (schematic designator SH1)
SH1_A3 "RF_SHIELD" RF_Sh 22.034,60.452 r0 top (schematic designator SH1)
SH1_A4 "RF_SHIELD" RF_Sh 22.098,51.435 r0 top (schematic designator SH1)
SH1_A5 "RF_SHIELD" RF_Sh 22.098,42.418 r0 top (schematic designator SH1)
SH1_A6 "RF_SHIELD" RF_Sh 22.098,33.401 r0 top (schematic designator SH1)
SH1_A7 "RF_SHIELD" RF_Sh 22.098,24.511 r0 top (schematic designator SH1)
SH1_A8 "RF_SHIELD" RF_Sh 22.098,15.494 r0 top (schematic designator SH1)
T1_M1 "ADTT1-1+" CD542_MNC 45.263,80.391 r180 top (schematic designator T1)
T1_M2 "ADTT1-1+" CD542_MNC 45.263,44.323 r180 top (schematic designator T1)
T3_M1 "ADTT1-1+" CD542_MNC 45.263,71.501 r180 top (schematic designator T3)
T3_M2 "ADTT1-1+" CD542_MNC 45.263,35.433 r180 top (schematic designator T3)
T4_M1 "ADTT1-1+" CD542_MNC 45.263,62.23 r180 top (schematic designator T4)
T4_M2 "ADTT1-1+" CD542_MNC 45.263,25.946 r180 top (schematic designator T4)
T5_M1 "ADTT1-1+" CD542_MNC 45.263,53.34 r180 top (schematic designator T5)
T5_M2 "ADTT1-1+" CD542_MNC 45.263,17.183 r180 top (schematic designator T5)
TP1 "+12V" TP_2X1.8 86.995,36.386 r270 top
TP2 "+3.3V" TP_2X1.8 72.319,45.553 r90 top
TP3 "+1.8V" TP_2X1.8 72.335,36.779 r90 top
TP4 "SyncIn" TP_2X1.8 61.087,58.293 r90 top
TP5 "SyncOut" TP_2X1.8 61.341,21.273 r270 top
TP6 "GND" TP_2X1.8 98.044,73.47 r270 top
TP7 "GND" TP_2X1.8 97.917,18.987 r0 top
U1_M1 "AD9959BCPZ" CP_56_1_ADI 56.816,67.12 r90 top (schematic designator U1)
U1_M2 "AD9959BCPZ" CP_56_1_ADI 56.868,30.838 r90 top (schematic designator U1)
U2 "MUN12AD03-SEC" SO8_MUN12AD_DEA 78.613,46.546 r270 top
U3 "MUN12AD03-SEC" SO8_MUN12AD_DEA 78.629,37.772 r270 top
U4_LS1 "74AVC4T774_GU" NXP_74AVC4T245GU,115 76.181,15.235 r90 top (schematic designator U4)
U4_LS2 "74AVC4T774_GU" NXP_74AVC4T245GU,115 71.701,15.235 r90 top (schematic designator U4)
U4_LS3 "74AVC4T774_GU" NXP_74AVC4T245GU,115 85.798,15.235 r90 top (schematic designator U4)
U4_LS4 "74AVC4T774_GU" NXP_74AVC4T245GU,115 80.718,15.235 r90 top (schematic designator U4)
U5_A1 "BGA2815,115" SOT_2815,115_NXP 25.03,79.296 r270 top (schematic designator U5)
U5_A2 "BGA2815,115" SOT_2815,115_NXP 23.506,68.518 r270 top (schematic designator U5)
U5_A3 "BGA2815,115" SOT_2815,115_NXP 23.506,59.518 r270 top (schematic designator U5)
U5_A4 "BGA2815,115" SOT_2815,115_NXP 23.506,50.518 r270 top (schematic designator U5)
U5_A5 "BGA2815,115" SOT_2815,115_NXP 23.506,41.518 r270 top (schematic designator U5)
U5_A6 "BGA2815,115" SOT_2815,115_NXP 23.506,32.518 r270 top (schematic designator U5)
U5_A7 "BGA2815,115" SOT_2815,115_NXP 23.506,23.518 r270 top (schematic designator U5)
U5_A8 "BGA2815,115" SOT_2815,115_NXP 23.506,14.518 r270 top (schematic designator U5)
U6_A1 "ADG901BCPZ-500RL7" CP_8_2_ADI 38.227,77.026 r180 top (schematic designator U6)
U6_A2 "ADG901BCPZ-500RL7" CP_8_2_ADI 38.227,67.899 r180 top (schematic designator U6)
U6_A3 "ADG901BCPZ-500RL7" CP_8_2_ADI 38.227,58.899 r180 top (schematic designator U6)
U6_A4 "ADG901BCPZ-500RL7" CP_8_2_ADI 38.227,49.899 r180 top (schematic designator U6)
U6_A5 "ADG901BCPZ-500RL7" CP_8_2_ADI 38.227,40.899 r180 top (schematic designator U6)
U6_A6 "ADG901BCPZ-500RL7" CP_8_2_ADI 38.227,31.899 r180 top (schematic designator U6)
U6_A7 "ADG901BCPZ-500RL7" CP_8_2_ADI 38.227,22.924 r180 top (schematic designator U6)
U6_A8 "ADG901BCPZ-500RL7" CP_8_2_ADI 38.227,13.907 r180 top (schematic designator U6)
Y1_M1 "ECS-250-20-33-CKM-TR3" SMD4_ECX-32_3P2X2P5_ECS 63.51,65.97 r0 bottom (schematic designator Y1)
Y1_M2 "ECS-250-20-33-CKM-TR3" SMD4_ECX-32_3P2X2P5_ECS 64.256,30.886 r0 bottom (schematic designator Y1)

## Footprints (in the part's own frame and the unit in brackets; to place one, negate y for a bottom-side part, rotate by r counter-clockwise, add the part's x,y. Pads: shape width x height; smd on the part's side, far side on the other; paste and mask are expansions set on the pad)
0402-A [mm] "Chip Inductor, Body 1.0x0.5mm, IPC High Density"
  rect 0.6x0.5 smd mask+0.051: 1(-0.5,0) 2(0.5,0)
  silkscreen extent -1.1,-0.15 -1.1,0.15, body extent -0.55,-0.3 0.55,0.3, height 0.55
1812_F [mm] "PTC RESETTABLE 33V 1.10A 1812L"
  rect 1.78x3.15 smd mask+0.051: 1(-2.665,0) 2(2.665,0)
  silkscreen extent -2.4,-1.7 2.4,1.7, body extent -2.36,-1.74 2.37,1.74, height 1.03
C0402 [mil]
  rect 25x25 smd mask+2: 1(-18.5,0) 2(20.9,0)
  silkscreen extent -36,-17 40,17, body extent -20,-12 20,12, height 8
C0603 [mm]
  rect 0.7x0.9 smd mask+0.051: 1(-0.7,0) 2(0.7,0)
  silkscreen extent -1.2,-0.6 1.2,0.6, body extent -0.8,-0.4 0.8,0.4, height 0.3
CD542_MNC [mm]
  rect 0.96x0.712 smd paste+0 mask+0.051: 1(-3.274,2.54) 2(-3.274,0) 3(-3.274,-2.54) 4(3.274,-2.54) 5(3.274,0) 6(3.274,2.54)
  silkscreen extent -2.92,-4.06 2.92,4.06, body extent -3.45,-3.94 3.45,3.94, height 2.85
CON_1053141204 [mm]
  rect 1.7x1.7 hole 1.2 mask+0.076: 1(0,0)
  round 1.7 hole 1.2 mask+0.076: 2(-2.5,0) 3(0,-2.5) 4(-2.5,-2.5)
  round 1.6 hole 1.6 unplated mask+0.076: 5(0,-9.68) 6(-2.5,-9.68)
  silkscreen extent -4.22,-12.88 3.5,0.64, body extent -4.24,-14.2 1.7,0.46, height 8.85
CONN_SMA-J-P-H-RA-TH1_SAI [mil]
  round 83 hole 63 mask+0: 1(0,0) 2(-100,100) 3(-100,-100) 4(100,-100) 5(100,100)
  silkscreen extent -143,-143 191,466, body extent -136,-137 140,457, height 372
CP_8_2_ADI [mm]
  rect 0.808x0.255 smd paste+0 mask+0.051: 1(-1.522,0.75) 2(-1.522,0.25) 3(-1.522,-0.25) 4(-1.522,-0.75) 5(1.522,-0.75) 6(1.522,-0.25) 7(1.522,0.25) 8(1.522,0.75)
  rect 1.6x1.88 smd paste+0 mask+0.051: 9(0,0)
  silkscreen extent -1.75,-1.75 1.75,1.75, body extent -1.63,-1.63 1.63,1.63, height 0.84
CP_56_1_ADI [mm]
  rect 0.808x0.255 smd paste+0 mask+0.051: 1(-3.896,3.25) 2(-3.896,2.75) 3(-3.896,2.25) 4(-3.896,1.75) 5(-3.896,1.25) 6(-3.896,0.75) 7(-3.896,0.25) 8(-3.896,-0.25) 9(-3.896,-0.75) 10(-3.896,-1.25) 11(-3.896,-1.75) 12(-3.896,-2.25) 13(-3.896,-2.75) 14(-3.896,-3.25) 29(3.896,-3.25) 30(3.896,-2.75) 31(3.896,-2.25) 32(3.896,-1.75) 33(3.896,-1.25) 34(3.896,-0.75) 35(3.896,-0.25) 36(3.896,0.25) 37(3.896,0.75) 38(3.896,1.25) 39(3.896,1.75) 40(3.896,2.25) 41(3.896,2.75) 42(3.896,3.25)
  rect 0.255x0.808 smd paste+0 mask+0.051: 15(-3.25,-3.896) 16(-2.75,-3.896) 17(-2.25,-3.896) 18(-1.75,-3.896) 19(-1.25,-3.896) 20(-0.75,-3.896) 21(-0.25,-3.896) 22(0.25,-3.896) 23(0.75,-3.896) 24(1.25,-3.896) 25(1.75,-3.896) 26(2.25,-3.896) 27(2.75,-3.896) 28(3.25,-3.896) 43(3.25,3.896) 44(2.75,3.896) 45(2.25,3.896) 46(1.75,3.896) 47(1.25,3.896) 48(0.75,3.896) 49(0.25,3.896) 50(-0.25,3.896) 51(-0.75,3.896) 52(-1.25,3.896) 53(-1.75,3.896) 54(-2.25,3.896) 55(-2.75,3.896) 56(-3.25,3.896)
  rect 6.248x6.248 smd paste-3.111 mask+0.051: 57(0,0)
  silkscreen extent -4.13,-4.13 4.13,4.13, body extent -4,-4 4,4, height 0.99
FB0603 [mm]
  rect 0.7x0.9 smd mask+0.051: 1(-0.7,0) 2(0.7,0)
  silkscreen extent -1.2,-0.6 1.2,0.6, body extent -0.76,-0.38 0.76,0.38, height 0.8
FIDUCIAL [mil]
  round 40 smd mask+20: 1(0,0)
  TOP_L1 pour cut-out: 43.31,0 43.31,4.27 41.64,12.63 38.38,20.51 33.64,27.61 27.61,33.64 20.51,38.38 12.63,41.64 4.27,43.31 0,43.31 -4.27,43.31 -12.63,41.64 -20.51,38.38 -27.61,33.64 -33.64,27.61 -38.38,20.51 -41.64,12.63 -43.31,4.27 -43.31,0 -43.31,-4.27 -41.64,-12.63 -38.38,-20.51 -33.64,-27.61 -27.61,-33.64 -20.51,-38.38 -12.63,-41.64 -4.27,-43.31 0,-43.31 4.27,-43.31 12.63,-41.64 20.51,-38.38 27.61,-33.64 33.64,-27.61 38.38,-20.51 41.64,-12.63 43.31,-4.27 43.31,0
HEADER_10X2 [mm]
  rect 1.7x1.7 hole 1.1 mask+0.05: 1(0,0)
  round 1.7 hole 1.1 mask+0.05: 2(0,2.54) 3(2.54,0) 4(2.54,2.54) 5(5.08,0) 6(5.08,2.54) 7(7.62,0) 8(7.62,2.54) 9(10.16,0) 10(10.16,2.54) 11(12.7,0) 12(12.7,2.54) 13(15.24,0) 14(15.24,2.54) 15(17.78,0) 16(17.78,2.54) 17(20.32,0) 18(20.32,2.54) 19(22.86,0) 20(22.86,2.54)
  silkscreen extent -1.27,-1.17 24.13,3.71, body extent -1.27,-1.27 24.13,3.81, height 7.75
"HOLE 3MM" [mm] "hole 3mm"
  round 4 hole 3.2: 1(0,0)
IND6X6_H3 [mm]
  rect 2.3x6.6 smd mask+0.051: 1(-2.15,0) 2(2.15,0)
  silkscreen extent -3.5,-3.56 3.5,3.5, body extent -3.1,-3.1 3.1,3.1, height 3.5
LED_0603_GREEN [mm] "LED 0603, Green"
  rect 0.7x0.9 smd mask+0.051: 1(-0.7,0) 2(0.7,0)
  silkscreen extent -1.14,-0.6 1.52,0.6, body extent -0.8,-0.4 0.8,0.4, height 0.7
MICTOR-38_PIN [mm]
  round 1.524 hole 2.43: 0(5.71,-3.495)
  rrect50% 0.43x1.6 smd mask+0.051: 1(0,0) 2(0,-6.99) 3(-0.635,0) 4(-0.635,-6.99) 5(-1.27,0) 6(-1.27,-6.99) 7(-1.905,0) 8(-1.905,-6.99) 9(-2.54,0) 10(-2.54,-6.99) 11(-3.175,0) 12(-3.175,-6.99) 13(-3.81,0) 14(-3.81,-6.99) 15(-4.445,0) 16(-4.445,-6.99) 17(-5.08,0) 18(-5.08,-6.99) 19(-5.715,0) 20(-5.715,-6.99) 21(-6.35,0) 22(-6.35,-6.99) 23(-6.985,0) 24(-6.985,-6.99) 25(-7.62,0) 26(-7.62,-6.99) 27(-8.255,0) 28(-8.255,-6.99) 29(-8.89,0) 30(-8.89,-6.99) 31(-9.525,0) 32(-9.525,-6.99) 33(-10.16,0) 34(-10.16,-6.99) 35(-10.795,0) 36(-10.795,-6.99) 37(-11.43,0) 38(-11.43,-6.99)
  round 1.2 hole 0.86: 39(-0.64,-3.495) 40(-3.18,-3.495) 41(-5.72,-3.495) 42(-8.26,-3.495) 43(-10.8,-3.495)
  silkscreen extent -18.8,-6.99 7.3,0, body extent -18.42,-7.85 6.98,0.86, height 6.05
NXP_74AVC4T245GU,115 [mm]
  rect 0.65x0.22 smd mask+0.051: 1(-0.725,0.6)
  rect 0.55x0.22 smd mask+0.051: 2(-0.775,0.2) 3(-0.775,-0.2) 4(-0.775,-0.6) 9(0.775,-0.6) 10(0.775,-0.2) 11(0.775,0.2) 12(0.775,0.6)
  rect 0.22x0.55 smd mask+0.051: 5(-0.6,-1.175) 6(-0.2,-1.175) 7(0.2,-1.175) 8(0.6,-1.175) 13(0.6,1.175) 14(0.2,1.175) 15(-0.2,1.175) 16(-0.6,1.175)
  silkscreen extent -1.05,-1.45 1.05,1.45, body extent -0.9,-1.3 0.9,1.3, height 0.5
PCIE_8LANE_EDGE [mil] "PCIE_8LANE_EDGE"
  rect 28x126 smd far side paste-100: A1(-984.25,-93.98)
  rect 28x169 smd far side paste-100: A2(-944.88,-115.48) A3(-905.51,-115.48) A4(-866.14,-115.48) A5(-826.77,-115.48) A6(-787.4,-115.48) A7(-748.03,-115.48) A8(-708.66,-115.48) A9(-669.29,-115.48) A10(-629.92,-115.48) A11(-590.55,-115.48) A12(-472.44,-115.48) A13(-433.07,-115.48) A14(-393.7,-115.48) A15(-354.33,-115.48) A16(-314.96,-115.48) A17(-275.59,-115.48) A18(-236.22,-115.48) A19(-196.85,-115.48) A20(-157.48,-115.48) A21(-118.11,-115.48) A22(-78.74,-115.48) A23(-39.37,-115.48) A24(0,-115.48) A25(39.37,-115.48) A26(78.74,-115.48) A27(118.11,-115.48) A28(157.48,-115.48) A29(196.85,-115.48) A30(236.22,-115.48) A31(275.59,-115.48) A32(314.96,-115.48)
  rect 28x169 smd paste-100 mask+2: B1(-984.25,-115.48) B2(-944.88,-115.48) B3(-905.51,-115.48) B4(-866.14,-115.48) B5(-826.77,-115.48) B6(-787.4,-115.48) B7(-748.03,-115.48) B8(-708.66,-115.48) B9(-669.29,-115.48) B10(-629.92,-115.48) B11(-590.55,-115.48) B12(-472.44,-115.48) B13(-433.07,-115.48) B14(-393.7,-115.48) B15(-354.33,-115.48) B16(-314.96,-115.48) B18(-236.22,-115.48) B19(-196.85,-115.48) B20(-157.48,-115.48) B21(-118.11,-115.48) B22(-78.74,-115.48) B23(-39.37,-115.48) B24(0,-115.48) B25(39.37,-115.48) B26(78.74,-115.48) B27(118.11,-115.48) B28(157.48,-115.48) B29(196.85,-115.48) B30(236.22,-115.48) B32(314.96,-115.48)
  rect 28x126 smd paste-100 mask+2: B17(-275.59,-93.98) B31(275.59,-93.98)
R0402 [mil] "R0402"
  rect 25x25 smd mask+2: 1(-18.5,0) 2(20.9,0)
  silkscreen extent -36,-17 40,17, body extent -20,-10 20,10, height 14
r0402 [mil] "R0402"
  rect 25x25 smd mask+2: 1(-18.5,0) 2(20.9,0)
  silkscreen extent -36,-17 40,17, body extent -20,-10 20,10, height 14
R0805 [mil] "R0805"
  rect 60x50 smd mask+2: 1(-45,0) 2(45,0)
  silkscreen extent -80,-30 80,30, body extent -39,-25 39,24, height 31
RF_Sh [mil]
  rect 60x125 smd mask+2: 1(-495,-112.5) 1(-495,112.5) 1(495,-112.5) 1(495,112.5)
  rect 115x60 smd mask+2: 1(-467.5,-145) 1(-467.5,145) 1(467.5,-145) 1(467.5,145)
  rect 140x60 smd mask+2: 1(-240,-145) 1(-240,145) 1(0,-145) 1(0,145) 1(240,-145) 1(240,145)
SAMTEC_MMCX-J-P-H-ST-TH1 [mm]
  round 1.348 hole 0.84: 1(0,0) S1(-1.27,1.27) S2(1.27,1.27) S3(1.27,-1.27) S4(-1.27,-1.27)
  silkscreen extent -1.75,-1.75 1.75,1.75, body extent -1.75,-1.75 1.75,1.75, height 4.35
SMD4_ECX-32_3P2X2P5_ECS [mm]
  rect 1.1x1.3 smd paste-0.55 mask+0.051: 1(-0.9,1.15) 2(-0.9,-1.15) 3(0.9,-1.15) 4(0.9,1.15)
  silkscreen extent -1.42,-0.17 1.42,0.17, body extent -1.3,-1.65 1.3,1.65, height 0.81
